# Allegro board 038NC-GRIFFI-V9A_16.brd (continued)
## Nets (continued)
S16_VBAT_F: SITE16.F1(VBAT_F) UNK16CS1.1 UNK16K10.3 UNK16K11.3 UNK16K12.3 UNK16TP_VBAT_F.1
S16_VBAT_K11C: UNK16C6.1 UNK16K11.4
S16_VBAT_K12: UNK16C9.1 UNK16K12.4 UNK16TP_REF_5V.1 UNK16U1.6
S16_VBAT_S: SITE16.S1(VBAT_S) UNK16K10.6 UNK16K12.6 UNK16TP_VBAT_S.1
S16_VBUS_CK: UNK16C2.2 UNK16K1.3
S16_VSET: SITE16.F8(VSET_F) SITE16.S8(VSET_S) UNK16K3.3 UNK16TP_VEST.1
S16_VSET_K3R: UNK16K3.2 UNK16R1.2
SCOPE_TP0: SLOT0.B16
SCOPE_TP1: SLOT0.A16
SDUABUS1: SLOT0.F41
SDUABUS2: SLOT0.E41
SDUABUS3: SLOT0.F39
SDUABUS4: SLOT0.E39
SDUCAL1_HF: SLOT0.A41
SDUCAL1_HG: SLOT0.A40 SLOT0.B40 SLOT0.C41
SDUCAL1_HS: SLOT0.B41
SDUCAL1_LF: SLOT0.A39
SDUCAL1_LS: SLOT0.B39
SDUCBIT1: SLOT0.D39 UNK1K7.8 UNK2K7.8
SDUCBIT2: SLOT0.C39 UNK1K6.8 UNK2K6.8
SDUCBIT3: SLOT0.F37 UNK1K4.8 UNK2K4.8
SDUCBIT4: SLOT0.E37 UNK1K5.8 UNK2K5.8
SDUCBIT5: SLOT0.D37 UNK1K3.8 UNK2K3.8
SDUCBIT6: SLOT0.C37 UNK1K10.8 UNK2K10.8
SDUCBIT7: SLOT0.F35 UNK1K12.8 UNK2K12.8
SDUCBIT8: SLOT0.E35 UNK1K11.8 UNK2K11.8
SDUCBIT9: SLOT0.D35 UNK1K13.8 UNK2K13.8
SDUCBIT10: SLOT0.C35 UNK1K8.8 UNK2K8.8
SDUCBIT11: SLOT0.B35 UNK1K1.8 UNK2K1.8
SDUCBIT12: SLOT0.A35 UNK1K14.8 UNK2K14.8
SDUCBIT13: SLOT0.F33 UNK1K9.8 UNK2K9.8
SDUCBIT14: SLOT0.E33 UNK1K2.8 UNK2K2.8
SDUCBIT15: SLOT0.D33
SDUCBIT16: SLOT0.C33
SDUCBIT17: SLOT0.B33 UNK3K7.8 UNK4K7.8
SDUCBIT18: SLOT0.A33 UNK3K6.8 UNK4K6.8
SDUCBIT19: SLOT0.F31 UNK3K4.8 UNK4K4.8
SDUCBIT20: SLOT0.E31 UNK3K5.8 UNK4K5.8
SDUCBIT21: SLOT0.D31 UNK3K3.8 UNK4K3.8
SDUCBIT22: SLOT0.C31 UNK3K10.8 UNK4K10.8
SDUCBIT23: SLOT0.B31 UNK3K12.8 UNK4K12.8
SDUCBIT24: SLOT0.A31 UNK3K11.8 UNK4K11.8
SDUCBIT25: SLOT0.F29 UNK3K13.8 UNK4K13.8
SDUCBIT26: SLOT0.E29 UNK3K8.8 UNK4K8.8
SDUCBIT27: SLOT0.D29 UNK3K1.8 UNK4K1.8
SDUCBIT28: SLOT0.C29 UNK3K14.8 UNK4K14.8
SDUCBIT29: SLOT0.B29 UNK3K9.8 UNK4K9.8
SDUCBIT30: SLOT0.A29 UNK3K2.8 UNK4K2.8
SDUCBIT31: SLOT0.F27
SDUCBIT32: SLOT0.E27
SDUCBIT33: SLOT0.D27 UNK5K7.8 UNK6K7.8
SDUCBIT34: SLOT0.C27 UNK5K6.8 UNK6K6.8
SDUCBIT35: SLOT0.B27 UNK5K4.8 UNK6K4.8
SDUCBIT36: SLOT0.A27 UNK5K5.8 UNK6K5.8
SDUCBIT37: SLOT0.F25 UNK5K3.8 UNK6K3.8
SDUCBIT38: SLOT0.E25 UNK5K10.8 UNK6K10.8
SDUCBIT39: SLOT0.D25 UNK5K12.8 UNK6K12.8
SDUCBIT40: SLOT0.C25 UNK5K11.8 UNK6K11.8
SDUCBIT41: SLOT0.B25 UNK5K13.8 UNK6K13.8
SDUCBIT42: SLOT0.A25 UNK5K8.8 UNK6K8.8
SDUCBIT43: SLOT0.F23 UNK5K1.8 UNK6K1.8
SDUCBIT44: SLOT0.E23 UNK5K14.8 UNK6K14.8
SDUCBIT45: SLOT0.D23 UNK5K9.8 UNK6K9.8
SDUCBIT46: SLOT0.C23 UNK5K2.8 UNK6K2.8
SDUCBIT47: SLOT0.B23
SDUCBIT48: SLOT0.A23
SDUCBIT49: SLOT0.F21 UNK7K7.8 UNK8K7.8
SDUCBIT50: SLOT0.E21 UNK7K6.8 UNK8K6.8
SDUCBIT51: SLOT0.D21 UNK7K4.8 UNK8K4.8
SDUCBIT52: SLOT0.C21 UNK7K5.8 UNK8K5.8
SDUCBIT53: SLOT0.B21 UNK7K3.8 UNK8K3.8
SDUCBIT54: SLOT0.A21 UNK7K10.8 UNK8K10.8
SDUCBIT55: SLOT0.F19 UNK7K12.8 UNK8K12.8
SDUCBIT56: SLOT0.E19 UNK7K11.8 UNK8K11.8
SDUCBIT57: SLOT0.D19 UNK7K13.8 UNK8K13.8
SDUCBIT58: SLOT0.C19 UNK7K8.8 UNK8K8.8
SDUCBIT59: SLOT0.B19 UNK7K1.8 UNK8K1.8
SDUCBIT60: SLOT0.A19 UNK7K14.8 UNK8K14.8
SDUCBIT61: SLOT0.F17 UNK7K9.8 UNK8K9.8
SDUCBIT62: SLOT0.E17 UNK7K2.8 UNK8K2.8
SDUCBIT63: SLOT0.D17
SDUCBIT64: SLOT0.F7
SDUCBIT65: SLOT0.E7 UNK9K7.8 UNK10K7.8
SDUCBIT66: SLOT0.D7 UNK9K6.8 UNK10K6.8
SDUCBIT67: SLOT0.C7 UNK9K4.8 UNK10K4.8
SDUCBIT68: SLOT0.B7 UNK9K5.8 UNK10K5.8
SDUCBIT69: SLOT0.A7 UNK9K3.8 UNK10K3.8
SDUCBIT70: SLOT0.F5 UNK9K10.8 UNK10K10.8
SDUCBIT71: SLOT0.E5 UNK9K12.8 UNK10K12.8
SDUCBIT72: SLOT0.D5 UNK9K11.8 UNK10K11.8
SDUCBIT73: SLOT0.C5 UNK9K13.8 UNK10K13.8
SDUCBIT74: SLOT0.B5 UNK9K8.8 UNK10K8.8
SDUCBIT75: SLOT0.A5 UNK9K1.8 UNK10K1.8
SDUCBIT76: SLOT0.F3 UNK9K14.8 UNK10K14.8
SDUCBIT77: SLOT0.E3 UNK9K9.8 UNK10K9.8
SDUCBIT78: SLOT0.D3 UNK9K2.8 UNK10K2.8
SDUCBIT79: SLOT0.C3
SDUCBIT80: SLOT0.B3
SDUCBIT81: SLOT0.A3 UNK11K7.8 UNK12K7.8
SDUCBIT82: SLOT0.G24 UNK11K6.8 UNK12K6.8
SDUCBIT83: SLOT0.F24 UNK11K4.8 UNK12K4.8
SDUCBIT84: SLOT0.E24 UNK11K5.8 UNK12K5.8
SDUCBIT85: SLOT0.D24 UNK11K3.8 UNK12K3.8
SDUCBIT86: SLOT0.C24 UNK11K10.8 UNK12K10.8
SDUCBIT87: SLOT0.B24 UNK11K12.8 UNK12K12.8
SDUCBIT88: SLOT0.F26 UNK11K11.8 UNK12K11.8
SDUCBIT89: SLOT0.E26 UNK11K13.8 UNK12K13.8
SDUCBIT90: SLOT0.D26 UNK11K8.8 UNK12K8.8
SDUCBIT91: SLOT0.C26 UNK11K1.8 UNK12K1.8
SDUCBIT92: SLOT0.B26 UNK11K14.8 UNK12K14.8
SDUCBIT93: SLOT0.A26 UNK11K9.8 UNK12K9.8
SDUCBIT94: SLOT0.G28 UNK11K2.8 UNK12K2.8
SDUCBIT95: SLOT0.F28
SDUCBIT96: SLOT0.E28
SDUCBIT97: SLOT0.D28 UNK13K7.8 UNK14K7.8
SDUCBIT98: SLOT0.C28 UNK13K6.8 UNK14K6.8
SDUCBIT99: SLOT0.B28 UNK13K4.8 UNK14K4.8
SDUCBIT100: SLOT0.F30 UNK13K5.8 UNK14K5.8
SDUCBIT101: SLOT0.E30 UNK13K3.8 UNK14K3.8
SDUCBIT102: SLOT0.D30 UNK13K10.8 UNK14K10.8
SDUCBIT103: SLOT0.C30 UNK13K12.8 UNK14K12.8
SDUCBIT104: SLOT0.B30 UNK13K11.8 UNK14K11.8
SDUCBIT105: SLOT0.A30 UNK13K13.8 UNK14K13.8
SDUCBIT106: SLOT0.G32 UNK13K8.8 UNK14K8.8
SDUCBIT107: SLOT0.F32 UNK13K1.8 UNK14K1.8
SDUCBIT108: SLOT0.E32 UNK13K14.8 UNK14K14.8
SDUCBIT109: SLOT0.D32 UNK13K9.8 UNK14K9.8
SDUCBIT110: SLOT0.C32 UNK13K2.8 UNK14K2.8
SDUCBIT111: SLOT0.B32
SDUCBIT112: SLOT0.F34
SDUCBIT113: SLOT0.E34 UNK15K7.8 UNK16K7.8
SDUCBIT114: SLOT0.D34 UNK15K6.8 UNK16K6.8
SDUCBIT115: SLOT0.C34 UNK15K4.8 UNK16K4.8
SDUCBIT116: SLOT0.B34 UNK15K5.8 UNK16K5.8
SDUCBIT117: SLOT0.A34 UNK15K3.8 UNK16K3.8
SDUCBIT118: SLOT0.G36 UNK15K10.8 UNK16K10.8
SDUCBIT119: SLOT0.F36 UNK15K12.8 UNK16K12.8
SDUCBIT120: SLOT0.E36 UNK15K11.8 UNK16K11.8
SDUCBIT121: SLOT0.D36 UNK15K13.8 UNK16K13.8
SDUCBIT122: SLOT0.C36 UNK15K8.8 UNK16K8.8
SDUCBIT123: SLOT0.B36 UNK15K1.8 UNK16K1.8
SDUCBIT124: SLOT0.G38 UNK15K14.8 UNK16K14.8
SDUCBIT125: SLOT0.F38 UNK15K9.8 UNK16K9.8
SDUCBIT126: SLOT0.E38 UNK15K2.8 UNK16K2.8
SDUCBIT127: SLOT0.D38
SDUCBIT128: SLOT0.C38
SDUI2C1_SYS_P3V3: R22.2 SLOT0.G16
SDUI2C1_SYS_SCLK: R24.2 SLOT0.G14 TP_EPP_SCLK.1(TP)
SDUI2C1_SYS_SDA: R23.2 SLOT0.G18
SDUI2C1_USER_SCLK: R8.2 SLOT0.F14 TP_USER_SCLK1.1(TP) U4.1(SCL)
SDUI2C1_USER_SDA: R7.2 SLOT0.F16 TP_USER_SDA1.1(TP) U4.2(SDA)
SDUP5V1: BC1.1 BC2.1 FUSE2.1 SLOT0.A2 SLOT0.A4 SLOT0.B2 SLOT0.B4 SLOT0.C2 T_USER_5V.1(TP) USER_5V1.1(A)
SDUSPI1_CS_N: SLOT0.E16
SDUSPI1_MISO: SLOT0.F18
SDUSPI1_MOSI: SLOT0.E18
SDUSPI1_SCLK: SLOT0.E14
SDUSYNC1: SLOT0.C14
SDUSYNC2: SLOT0.B14
SPARE0: SLOT0.A8
SPARE1: SLOT0.G22
SPARE2: SLOT0.A20
SPARE3: SLOT0.G26
SPARE4: SLOT0.A24
SPARE5: SLOT0.G30
SPARE6: SLOT0.A28
SPARE7: SLOT0.G34
SPARE8: SLOT0.A32
SPARE9: SLOT0.G40
SPARE10: SLOT0.A36
SPARE11: SLOT0.F40
SPARE12: SLOT0.C40
SPARE13: SLOT0.E40
SPARE14: SLOT0.D40
TMU_INPUT_A: SLOT0.B12
TMU_INPUT_B: SLOT0.D12
TMU_REF_GND: SLOT0.A37 UNK0BS1.1
TMU_TRIGGER: SLOT0.F12
U4_CT: R9.2 U4.10(CT)
U4_INT: R10.2 U4.9(INT)
U6_SCL: R24.1 U6.6(SCL)
U6_SDA: R21.2 R23.1 TP_EPP_SDA.1(TP) U6.5(SDA)
U6_VCC: C14.2 R21.1 R22.1 TP_EPP_VCC.1(TP) U6.8(VCC)
U46_ADJ: R376.2 R381.1 U46.1(ADJ)
U46_R: R381.2 R382.1
U47_ADJ: R378.1 R383.2 U47.1(ADJ)
UGND: BC1.2 BC2.2 BC3.1 BC4.1 BC5.2 BC6.2 BC7.2 BC8.2 BC10.2 BC11.2 BC12.1 BC13.1 BD1.2 BD2.2 C102.2
USER_12V: BC7.1 BC8.1 SLOT0.F6 SLOT0.G6 T_USER_12V.1(TP) UNK1C7.1 UNK1C8.1 UNK1K1.1 UNK1K2.1 UNK1K3.1 UNK1K4.1 UNK1K5.1 UNK1K6.1 UNK1K7.1 UNK1K8.1 UNK1K9.1 UNK1K10.1 UNK1K11.1 UNK1K12.1 UNK1K13.1 UNK1K14.1 UNK1U1.2 UNK2C7.1 UNK2C8.1 UNK2K1.1 UNK2K2.1 UNK2K3.1 UNK2K4.1 UNK2K5.1 UNK2K6.1 UNK2K7.1 UNK2K8.1 UNK2K9.1 UNK2K10.1 UNK2K11.1 UNK2K12.1 UNK2K13.1 UNK2K14.1 UNK2U1.2 UNK3C7.1 UNK3C8.1 UNK3K1.1 UNK3K2.1 UNK3K3.1 UNK3K4.1 UNK3K5.1 UNK3K6.1 UNK3K7.1 UNK3K8.1 UNK3K9.1 UNK3K10.1 UNK3K11.1 UNK3K12.1 UNK3K13.1 UNK3K14.1 UNK3U1.2 UNK4C7.1 UNK4C8.1 UNK4K1.1 UNK4K2.1 UNK4K3.1 UNK4K4.1 UNK4K5.1 UNK4K6.1 UNK4K7.1 UNK4K8.1 UNK4K9.1 UNK4K10.1 UNK4K11.1 UNK4K12.1 UNK4K13.1 UNK4K14.1 UNK4U1.2 UNK5C7.1 UNK5C8.1 UNK5K1.1 UNK5K2.1 UNK5K3.1 UNK5K4.1 UNK5K5.1 UNK5K6.1 UNK5K7.1 UNK5K8.1 UNK5K9.1 UNK5K10.1 UNK5K11.1 UNK5K12.1 UNK5K13.1 UNK5K14.1 UNK5U1.2 UNK6C7.1 UNK6C8.1 UNK6K1.1 UNK6K2.1 UNK6K3.1 UNK6K4.1 UNK6K5.1 UNK6K6.1 UNK6K7.1 UNK6K8.1 UNK6K9.1 UNK6K10.1 UNK6K11.1 UNK6K12.1 UNK6K13.1 UNK6K14.1 UNK6U1.2 UNK7C7.1 UNK7C8.1 UNK7K1.1 UNK7K2.1 UNK7K3.1 UNK7K4.1 UNK7K5.1 UNK7K6.1 UNK7K7.1 UNK7K8.1 UNK7K9.1 UNK7K10.1 UNK7K11.1 UNK7K12.1 UNK7K13.1 UNK7K14.1 UNK7U1.2 UNK8C7.1 UNK8C8.1 UNK8K1.1 UNK8K2.1 UNK8K3.1 UNK8K4.1 UNK8K5.1 UNK8K6.1 UNK8K7.1 UNK8K8.1 UNK8K9.1 UNK8K10.1 UNK8K11.1 UNK8K12.1 UNK8K13.1 UNK8K14.1 UNK8U1.2 UNK9C7.1 UNK9C8.1 UNK9K1.1 UNK9K2.1 UNK9K3.1 UNK9K4.1 UNK9K5.1 UNK9K6.1 UNK9K7.1 UNK9K8.1 UNK9K9.1 UNK9K10.1 UNK9K11.1 UNK9K12.1 UNK9K13.1 UNK9K14.1 UNK9U1.2 UNK10C7.1 UNK10C8.1 UNK10K1.1 UNK10K2.1 UNK10K3.1 UNK10K4.1 UNK10K5.1 UNK10K6.1 UNK10K7.1 UNK10K8.1 UNK10K9.1 UNK10K10.1 UNK10K11.1 UNK10K12.1 UNK10K13.1 UNK10K14.1 UNK10U1.2 UNK11C7.1 UNK11C8.1 UNK11K1.1 UNK11K2.1 UNK11K3.1 UNK11K4.1 UNK11K5.1 UNK11K6.1 UNK11K7.1 UNK11K8.1 UNK11K9.1 UNK11K10.1 UNK11K11.1 UNK11K12.1 UNK11K13.1 UNK11K14.1 UNK11U1.2 UNK12C7.1 UNK12C8.1 UNK12K1.1 UNK12K2.1 UNK12K3.1 UNK12K4.1 UNK12K5.1 UNK12K6.1 UNK12K7.1 UNK12K8.1 UNK12K9.1 UNK12K10.1 UNK12K11.1 UNK12K12.1 UNK12K13.1 UNK12K14.1 UNK12U1.2 UNK13C7.1 UNK13C8.1 UNK13K1.1 UNK13K2.1 UNK13K3.1 UNK13K4.1 UNK13K5.1 UNK13K6.1 UNK13K7.1 UNK13K8.1 UNK13K9.1 UNK13K10.1 UNK13K11.1 UNK13K12.1 UNK13K13.1 UNK13K14.1 UNK13U1.2 UNK14C7.1 UNK14C8.1 UNK14K1.1 UNK14K2.1 UNK14K3.1 UNK14K4.1 UNK14K5.1 UNK14K6.1 UNK14K7.1 UNK14K8.1 UNK14K9.1 UNK14K10.1 UNK14K11.1 UNK14K12.1 UNK14K13.1 UNK14K14.1 UNK14U1.2 UNK15C7.1 UNK15C8.1 UNK15K1.1 UNK15K2.1 UNK15K3.1 UNK15K4.1 UNK15K5.1 UNK15K6.1 UNK15K7.1 UNK15K8.1 UNK15K9.1 UNK15K10.1 UNK15K11.1 UNK15K12.1 UNK15K13.1 UNK15K14.1 UNK15U1.2 UNK16C7.1 UNK16C8.1 UNK16K1.1 UNK16K2.1 UNK16K3.1 UNK16K4.1 UNK16K5.1 UNK16K6.1 UNK16K7.1 UNK16K8.1 UNK16K9.1 UNK16K10.1 UNK16K11.1 UNK16K12.1 UNK16K13.1 UNK16K14.1 UNK16U1.2 USER_12V1.1(A)
USER_-5V: BC3.2 BC4.2 BR2.2 SLOT0.C4 SLOT0.D4 SLOT0.E4 SLOT0.F4 SLOT0.G4 T_USER_-5V.1(TP)
VI_433_6-CH1BP: SLOT6.B35
VI_433_6-CH1F: SLOT6.F35
VI_433_6-CH1GS: SLOT6.A35
VI_433_6-CH1S: SLOT6.C35
VI_434_6-CH2BP: SLOT6.B33
VI_434_6-CH2F: SLOT6.F33
VI_434_6-CH2GS: SLOT6.A33
VI_434_6-CH2S: SLOT6.C33
VI_435_6-CH3BP: SLOT6.B31
VI_435_6-CH3F: SLOT6.F31
VI_435_6-CH3GS: SLOT6.A31
VI_435_6-CH3S: SLOT6.C31
VI_436_6-CH4BP: SLOT6.B29
VI_436_6-CH4F: SLOT6.F29
VI_436_6-CH4GS: SLOT6.A29
VI_436_6-CH4S: SLOT6.C29
VI_437_6-CH5BP: SLOT6.B27
VI_437_6-CH5F: SLOT6.F27
VI_437_6-CH5GS: SLOT6.A27
VI_437_6-CH5S: SLOT6.C27
VI_438_6-CH6BP: SLOT6.B25
VI_438_6-CH6F: SLOT6.F25
VI_438_6-CH6GS: SLOT6.A25
VI_438_6-CH6S: SLOT6.C25
VI_439_6-CH7BP: SLOT6.B23
VI_439_6-CH7F: SLOT6.F23
VI_439_6-CH7GS: SLOT6.A23
VI_439_6-CH7S: SLOT6.C23
VI_440_6-CH8BP: SLOT6.B21
VI_440_6-CH8F: SLOT6.F21
VI_440_6-CH8GS: SLOT6.A21
VI_440_6-CH8S: SLOT6.C21
VI_441_6-CH9BP: SLOT6.D37
VI_441_6-CH9F: SLOT6.F37
VI_441_6-CH9GS: SLOT6.C37
VI_441_6-CH9S: SLOT6.E37
VI_442_6-CH10BP: SLOT6.D33
VI_442_6-CH10F: SLOT6.E35
VI_442_6-CH10GS: SLOT6.B37
VI_442_6-CH10S: SLOT6.E33
VI_443_6-CH11BP: SLOT6.D29
VI_443_6-CH11F: SLOT6.E31
VI_443_6-CH11GS: SLOT6.A37
VI_443_6-CH11S: SLOT6.E29
VI_444_6-CH12BP: SLOT6.D25
VI_444_6-CH12F: SLOT6.E27
VI_444_6-CH12GS: SLOT6.B19
VI_444_6-CH12S: SLOT6.E25
VI_445_6-CH13BP: SLOT6.D21
VI_445_6-CH13F: SLOT6.E23
VI_445_6-CH13GS: SLOT6.A19
VI_445_6-CH13S: SLOT6.E21
VI_446_6-CH14BP: SLOT6.D19
VI_446_6-CH14F: SLOT6.F19
VI_446_6-CH14GS: SLOT6.C19
VI_446_6-CH14S: SLOT6.E19
VI_447_6-CH15BP: SLOT6.D17
VI_447_6-CH15F: SLOT6.F17
VI_447_6-CH15GS: SLOT6.A17
VI_447_6-CH15S: SLOT6.E17
VI_448_6-CH16BP: SLOT6.C17
VI_448_6-CH16F: SLOT6.E15
VI_448_6-CH16GS: SLOT6.B17
VI_448_6-CH16S: SLOT6.D15
VI_449_6-CH17BP: SLOT6.B15
VI_449_6-CH17F: SLOT6.F15
VI_449_6-CH17GS: SLOT6.A15
VI_449_6-CH17S: SLOT6.C15
VI_450_6-CH18BP: SLOT6.D13
VI_450_6-CH18F: SLOT6.F13
VI_450_6-CH18GS: SLOT6.A13
VI_450_6-CH18S: SLOT6.E13
VI_451_6-CH19BP: SLOT6.D11
VI_451_6-CH19F: SLOT6.F11
VI_451_6-CH19GS: SLOT6.B13
VI_451_6-CH19S: SLOT6.E11
VI_452_6-CH20BP: SLOT6.C11
VI_452_6-CH20F: SLOT6.E9
VI_452_6-CH20GS: SLOT6.C13
VI_452_6-CH20S: SLOT6.D9
VI_453_6-CH21BP: SLOT6.B9
VI_453_6-CH21F: SLOT6.F9
VI_453_6-CH21GS: SLOT6.B11
VI_453_6-CH21S: SLOT6.C9
VI_454_6-CH22BP: SLOT6.D7
VI_454_6-CH22F: SLOT6.F7
VI_454_6-CH22GS: SLOT6.A11
VI_454_6-CH22S: SLOT6.E7
VI_455_6-CH23BP: SLOT6.D5
VI_455_6-CH23F: SLOT6.F5
VI_455_6-CH23GS: SLOT6.A9
VI_455_6-CH23S: SLOT6.E5
VI_456_6-CH24BP: SLOT6.D3
VI_456_6-CH24F: SLOT6.F3
VI_456_6-CH24GS: SLOT6.A7
VI_456_6-CH24S: SLOT6.E3
VI_457_6-CH25BP: SLOT6.D1
VI_457_6-CH25F: SLOT6.F1
VI_457_6-CH25GS: SLOT6.B7
VI_457_6-CH25S: SLOT6.E1
VI_458_6-CH26BP: SLOT6.C3
VI_458_6-CH26F: SLOT6.G4
VI_458_6-CH26GS: SLOT6.C7
VI_458_6-CH26S: SLOT6.C1
VI_459_6-CH27BP: SLOT6.D2
VI_459_6-CH27F: SLOT6.F2
VI_459_6-CH27GS: SLOT6.C5
VI_459_6-CH27S: SLOT6.C4
VI_460_6-CH28BP: SLOT6.B3
VI_460_6-CH28F: SLOT6.A4
VI_460_6-CH28GS: SLOT6.B5
VI_460_6-CH28S: SLOT6.B1
VI_461_6-CH29BP: SLOT6.A3
VI_461_6-CH29F: SLOT6.B2
VI_461_6-CH29GS: SLOT6.A5
VI_461_6-CH29S: SLOT6.A1
VI_462_6-CH30BP: SLOT6.A60
VI_462_6-CH30F: SLOT6.B62
VI_462_6-CH30GS: SLOT6.B58
VI_462_6-CH30S: SLOT6.A61
VI_463_6-CH31BP: SLOT6.A59
VI_463_6-CH31F: SLOT6.C62
VI_463_6-CH31GS: SLOT6.A57
VI_463_6-CH31S: SLOT6.B61
VI_464_6-CH32BP: SLOT6.E60
VI_464_6-CH32F: SLOT6.F62
VI_464_6-CH32GS: SLOT6.C60
VI_464_6-CH32S: SLOT6.F61
VI_465_6-CH33BP: SLOT6.D61
VI_465_6-CH33F: SLOT6.E62
VI_465_6-CH33GS: SLOT6.C61
VI_465_6-CH33S: SLOT6.E61
VI_466_6-CH34BP: SLOT6.C59
VI_466_6-CH34F: SLOT6.F59
VI_466_6-CH34GS: SLOT6.B59
VI_466_6-CH34S: SLOT6.D59
VI_467_6-CH35BP: SLOT6.F58
VI_467_6-CH35F: SLOT6.G60
VI_467_6-CH35GS: SLOT6.D58
VI_467_6-CH35S: SLOT6.E59
VI_468_6-CH36BP: SLOT6.C57
VI_468_6-CH36F: SLOT6.E57
VI_468_6-CH36GS: SLOT6.B57
VI_468_6-CH36S: SLOT6.D57
VI_469_6-CH37BP: SLOT6.E56
VI_469_6-CH37F: SLOT6.F57
VI_469_6-CH37GS: SLOT6.C56
VI_469_6-CH37S: SLOT6.G56
VI_470_6-CH38BP: SLOT6.D55
VI_470_6-CH38F: SLOT6.F55
VI_470_6-CH38GS: SLOT6.B55
VI_470_6-CH38S: SLOT6.E55
VI_471_6-CH39BP: SLOT6.B54
VI_471_6-CH39F: SLOT6.E52
VI_471_6-CH39GS: SLOT6.A55
VI_471_6-CH39S: SLOT6.C55
VI_472_6-CH40BP: SLOT6.D54
VI_472_6-CH40F: SLOT6.G52
VI_472_6-CH40GS: SLOT6.A56
VI_472_6-CH40S: SLOT6.F54
VI_473_6-CH41BP: SLOT6.B53
VI_473_6-CH41F: SLOT6.F53
VI_473_6-CH41GS: SLOT6.A53
VI_473_6-CH41S: SLOT6.C53
VI_474_6-CH42BP: SLOT6.D53
VI_474_6-CH42F: SLOT6.F51
VI_474_6-CH42GS: SLOT6.A52
VI_474_6-CH42S: SLOT6.E53
VI_475_6-CH43BP: SLOT6.C51
VI_475_6-CH43F: SLOT6.E51
VI_475_6-CH43GS: SLOT6.C52
VI_475_6-CH43S: SLOT6.D51
VI_476_6-CH44BP: SLOT6.D50
VI_476_6-CH44F: SLOT6.F49
VI_476_6-CH44GS: SLOT6.A51
VI_476_6-CH44S: SLOT6.F50
VI_477_6-CH45BP: SLOT6.B50
VI_477_6-CH45F: SLOT6.E49
VI_477_6-CH45GS: SLOT6.B51
VI_477_6-CH45S: SLOT6.D49
VI_478_6-CH46BP: SLOT6.B49
VI_478_6-CH46F: SLOT6.G48
VI_478_6-CH46GS: SLOT6.A49
VI_478_6-CH46S: SLOT6.C49
VI_479_6-CH47BP: SLOT6.D47
VI_479_6-CH47F: SLOT6.F47
VI_479_6-CH47GS: SLOT6.A48
VI_479_6-CH47S: SLOT6.E47
VI_480_6-CH48BP: SLOT6.C45
VI_480_6-CH48F: SLOT6.F45
VI_480_6-CH48GS: SLOT6.C48
VI_480_6-CH48S: SLOT6.D46
VI_481_6-CH49BP: SLOT6.C47
VI_481_6-CH49F: SLOT6.F46
VI_481_6-CH49GS: SLOT6.E48
VI_481_6-CH49S: SLOT6.E45
VI_482_6-CH50BP: SLOT6.B46
VI_482_6-CH50F: SLOT6.G44
VI_482_6-CH50GS: SLOT6.B47
VI_482_6-CH50S: SLOT6.B45
VI_483_6-CH51BP: SLOT6.D45
VI_483_6-CH51F: SLOT6.F41
VI_483_6-CH51GS: SLOT6.A47
VI_483_6-CH51S: SLOT6.E43
VI_484_6-CH52BP: SLOT6.D43
VI_484_6-CH52F: SLOT6.F43
VI_484_6-CH52GS: SLOT6.A45
VI_484_6-CH52S: SLOT6.F42
VI_485_6-CH53BP: SLOT6.D42
VI_485_6-CH53F: SLOT6.G40
VI_485_6-CH53GS: SLOT6.A44
VI_485_6-CH53S: SLOT6.E41
VI_486_6-CH54BP: SLOT6.C41
VI_486_6-CH54F: SLOT6.F39
VI_486_6-CH54GS: SLOT6.C44
VI_486_6-CH54S: SLOT6.D41
VI_487_6-CH55BP: SLOT6.B41
VI_487_6-CH55F: SLOT6.F38
VI_487_6-CH55GS: SLOT6.E44
VI_487_6-CH55S: SLOT6.B39
VI_488_6-CH56BP: SLOT6.C39
VI_488_6-CH56F: SLOT6.E39
VI_488_6-CH56GS: SLOT6.C43
VI_488_6-CH56S: SLOT6.D39
VI_489_6-CH57BP: SLOT6.A41
VI_489_6-CH57F: SLOT6.E40
VI_489_6-CH57GS: SLOT6.B43
VI_489_6-CH57S: SLOT6.A39
VI_490_6-CH58BP: SLOT6.B42
VI_490_6-CH58F: SLOT6.C40
VI_490_6-CH58GS: SLOT6.A43
VI_490_6-CH58S: SLOT6.A40
VI_491_6-CH59BP: SLOT6.C36
VI_491_6-CH59F: SLOT6.G36
VI_491_6-CH59GS: SLOT6.D38
VI_491_6-CH59S: SLOT6.E36
VI_492_6-CH60BP: SLOT6.D34
VI_492_6-CH60F: SLOT6.G32
VI_492_6-CH60GS: SLOT6.B38
VI_492_6-CH60S: SLOT6.E32
VI_493_6-CH61BP: SLOT6.E24
VI_493_6-CH61F: SLOT6.E28
VI_493_6-CH61GS: SLOT6.A36
VI_493_6-CH61S: SLOT6.F26
VI_494_6-CH62BP: SLOT6.F18
VI_494_6-CH62F: SLOT6.G20
VI_494_6-CH62GS: SLOT6.B10
VI_494_6-CH62S: SLOT6.E16
VI_495_6-CH63BP: SLOT6.E12
VI_495_6-CH63F: SLOT6.F14
VI_495_6-CH63GS: SLOT6.A8
VI_495_6-CH63S: SLOT6.D10
VI_496_6-CH64BP: SLOT6.E8
VI_496_6-CH64F: SLOT6.G8
VI_496_6-CH64GS: SLOT6.C8
VI_496_6-CH64S: SLOT6.F6
VI_497_6-CH65BP: SLOT6.B34
VI_497_6-CH65F: SLOT6.F34
VI_497_6-CH65GS: SLOT6.A32
VI_497_6-CH65S: SLOT6.C32
VI_498_6-CH66BP: SLOT6.D30
VI_498_6-CH66F: SLOT6.F30
VI_498_6-CH66GS: SLOT6.B30
VI_498_6-CH66S: SLOT6.C28
VI_499_6-CH67BP: SLOT6.B26
VI_499_6-CH67F: SLOT6.G28
VI_499_6-CH67GS: SLOT6.A28
VI_499_6-CH67S: SLOT6.D26
VI_500_6-CH68BP: SLOT6.C24
VI_500_6-CH68F: SLOT6.G24
VI_500_6-CH68GS: SLOT6.A24
VI_500_6-CH68S: SLOT6.B22
VI_501_6-CH69BP: SLOT6.C20
VI_501_6-CH69F: SLOT6.F22
VI_501_6-CH69GS: SLOT6.A20
VI_501_6-CH69S: SLOT6.D22
VI_502_6-CH70BP: SLOT6.D18
VI_502_6-CH70F: SLOT6.G16
VI_502_6-CH70GS: SLOT6.B18
VI_502_6-CH70S: SLOT6.E20
VI_503_6-CH71BP: SLOT6.C16
VI_503_6-CH71F: SLOT6.G12
VI_503_6-CH71GS: SLOT6.A16
VI_503_6-CH71S: SLOT6.B14
VI_504_6-CH72BP: SLOT6.C12
VI_504_6-CH72F: SLOT6.F10
VI_504_6-CH72GS: SLOT6.A12
VI_504_6-CH72S: SLOT6.D14
VI_505_7-CH1BP: SLOT7.B35
VI_505_7-CH1F: SLOT7.F35
VI_505_7-CH1GS: SLOT7.A35
VI_505_7-CH1S: SLOT7.C35
VI_506_7-CH2BP: SLOT7.B33
VI_506_7-CH2F: SLOT7.F33
VI_506_7-CH2GS: SLOT7.A33
VI_506_7-CH2S: SLOT7.C33
VI_507_7-CH3BP: SLOT7.B31
VI_507_7-CH3F: SLOT7.F31
VI_507_7-CH3GS: SLOT7.A31
VI_507_7-CH3S: SLOT7.C31
VI_508_7-CH4BP: SLOT7.B29
VI_508_7-CH4F: SLOT7.F29
VI_508_7-CH4GS: SLOT7.A29
VI_508_7-CH4S: SLOT7.C29
VI_509_7-CH5BP: SLOT7.B27
VI_509_7-CH5F: SLOT7.F27
VI_509_7-CH5GS: SLOT7.A27
VI_509_7-CH5S: SLOT7.C27
VI_510_7-CH6BP: SLOT7.B25
VI_510_7-CH6F: SLOT7.F25
VI_510_7-CH6GS: SLOT7.A25
VI_510_7-CH6S: SLOT7.C25
VI_511_7-CH7BP: SLOT7.B23
VI_511_7-CH7F: SLOT7.F23
VI_511_7-CH7GS: SLOT7.A23
VI_511_7-CH7S: SLOT7.C23
VI_512_7-CH8BP: SLOT7.B21
VI_512_7-CH8F: SLOT7.F21
VI_512_7-CH8GS: SLOT7.A21
VI_512_7-CH8S: SLOT7.C21
VI_513_7-CH9BP: SLOT7.D37
VI_513_7-CH9F: SLOT7.F37
VI_513_7-CH9GS: SLOT7.C37
VI_513_7-CH9S: SLOT7.E37
VI_514_7-CH10BP: SLOT7.D33
VI_514_7-CH10F: SLOT7.E35
VI_514_7-CH10GS: SLOT7.B37
VI_514_7-CH10S: SLOT7.E33
VI_515_7-CH11BP: SLOT7.D29
VI_515_7-CH11F: SLOT7.E31
VI_515_7-CH11GS: SLOT7.A37
VI_515_7-CH11S: SLOT7.E29
VI_516_7-CH12BP: SLOT7.D25
VI_516_7-CH12F: SLOT7.E27
VI_516_7-CH12GS: SLOT7.B19
VI_516_7-CH12S: SLOT7.E25
VI_517_7-CH13BP: SLOT7.D21
VI_517_7-CH13F: SLOT7.E23
VI_517_7-CH13GS: SLOT7.A19
VI_517_7-CH13S: SLOT7.E21
VI_518_7-CH14BP: SLOT7.D19
VI_518_7-CH14F: SLOT7.F19
VI_518_7-CH14GS: SLOT7.C19
VI_518_7-CH14S: SLOT7.E19
VI_519_7-CH15BP: SLOT7.D17
VI_519_7-CH15F: SLOT7.F17
VI_519_7-CH15GS: SLOT7.A17
VI_519_7-CH15S: SLOT7.E17
VI_520_7-CH16BP: SLOT7.C17
VI_520_7-CH16F: SLOT7.E15
VI_520_7-CH16GS: SLOT7.B17
VI_520_7-CH16S: SLOT7.D15
VI_521_7-CH17BP: SLOT7.B15
VI_521_7-CH17F: SLOT7.F15
VI_521_7-CH17GS: SLOT7.A15
VI_521_7-CH17S: SLOT7.C15
VI_522_7-CH18BP: SLOT7.D13
VI_522_7-CH18F: SLOT7.F13
VI_522_7-CH18GS: SLOT7.A13
VI_522_7-CH18S: SLOT7.E13
VI_523_7-CH19BP: SLOT7.D11
VI_523_7-CH19F: SLOT7.F11
VI_523_7-CH19GS: SLOT7.B13
VI_523_7-CH19S: SLOT7.E11
VI_524_7-CH20BP: SLOT7.C11
VI_524_7-CH20F: SLOT7.E9
VI_524_7-CH20GS: SLOT7.C13
VI_524_7-CH20S: SLOT7.D9
VI_525_7-CH21BP: SLOT7.B9
VI_525_7-CH21F: SLOT7.F9
VI_525_7-CH21GS: SLOT7.B11
VI_525_7-CH21S: SLOT7.C9
VI_526_7-CH22BP: SLOT7.D7
VI_526_7-CH22F: SLOT7.F7
VI_526_7-CH22GS: SLOT7.A11
VI_526_7-CH22S: SLOT7.E7
VI_527_7-CH23BP: SLOT7.D5
VI_527_7-CH23F: SLOT7.F5
VI_527_7-CH23GS: SLOT7.A9
VI_527_7-CH23S: SLOT7.E5
VI_528_7-CH24BP: SLOT7.D3
VI_528_7-CH24F: SLOT7.F3
VI_528_7-CH24GS: SLOT7.A7
VI_528_7-CH24S: SLOT7.E3
VI_529_7-CH25BP: SLOT7.D1
VI_529_7-CH25F: SLOT7.F1
VI_529_7-CH25GS: SLOT7.B7
VI_529_7-CH25S: SLOT7.E1
VI_530_7-CH26BP: SLOT7.C3
VI_530_7-CH26F: SLOT7.G4
VI_530_7-CH26GS: SLOT7.C7
VI_530_7-CH26S: SLOT7.C1
VI_531_7-CH27BP: SLOT7.D2
VI_531_7-CH27F: SLOT7.F2
VI_531_7-CH27GS: SLOT7.C5
VI_531_7-CH27S: SLOT7.C4
VI_532_7-CH28BP: SLOT7.B3
VI_532_7-CH28F: SLOT7.A4
VI_532_7-CH28GS: SLOT7.B5
VI_532_7-CH28S: SLOT7.B1
VI_533_7-CH29BP: SLOT7.A3
VI_533_7-CH29F: SLOT7.B2
VI_533_7-CH29GS: SLOT7.A5
VI_533_7-CH29S: SLOT7.A1
VI_534_7-CH30BP: SLOT7.A60
VI_534_7-CH30F: SLOT7.B62
VI_534_7-CH30GS: SLOT7.B58
VI_534_7-CH30S: SLOT7.A61
VI_535_7-CH31BP: SLOT7.A59
VI_535_7-CH31F: SLOT7.C62
VI_535_7-CH31GS: SLOT7.A57
VI_535_7-CH31S: SLOT7.B61
VI_536_7-CH32BP: SLOT7.E60
VI_536_7-CH32F: SLOT7.F62
VI_536_7-CH32GS: SLOT7.C60
VI_536_7-CH32S: SLOT7.F61
VI_537_7-CH33BP: SLOT7.D61
VI_537_7-CH33F: SLOT7.E62
VI_537_7-CH33GS: SLOT7.C61
VI_537_7-CH33S: SLOT7.E61
VI_538_7-CH34BP: SLOT7.C59
VI_538_7-CH34F: SLOT7.F59
VI_538_7-CH34GS: SLOT7.B59
VI_538_7-CH34S: SLOT7.D59
VI_539_7-CH35BP: SLOT7.F58
VI_539_7-CH35F: SLOT7.G60
VI_539_7-CH35GS: SLOT7.D58
VI_539_7-CH35S: SLOT7.E59
VI_540_7-CH36BP: SLOT7.C57
VI_540_7-CH36F: SLOT7.E57
VI_540_7-CH36GS: SLOT7.B57
VI_540_7-CH36S: SLOT7.D57
VI_541_7-CH37BP: SLOT7.E56
VI_541_7-CH37F: SLOT7.F57
VI_541_7-CH37GS: SLOT7.C56
VI_541_7-CH37S: SLOT7.G56
VI_542_7-CH38BP: SLOT7.D55
VI_542_7-CH38F: SLOT7.F55
VI_542_7-CH38GS: SLOT7.B55
VI_542_7-CH38S: SLOT7.E55
VI_543_7-CH39BP: SLOT7.B54
VI_543_7-CH39F: SLOT7.E52
VI_543_7-CH39GS: SLOT7.A55
VI_543_7-CH39S: SLOT7.C55
VI_544_7-CH40BP: SLOT7.D54
VI_544_7-CH40F: SLOT7.G52
VI_544_7-CH40GS: SLOT7.A56
VI_544_7-CH40S: SLOT7.F54
VI_545_7-CH41BP: SLOT7.B53
VI_545_7-CH41F: SLOT7.F53
VI_545_7-CH41GS: SLOT7.A53
VI_545_7-CH41S: SLOT7.C53
VI_546_7-CH42BP: SLOT7.D53
VI_546_7-CH42F: SLOT7.F51
VI_546_7-CH42GS: SLOT7.A52
VI_546_7-CH42S: SLOT7.E53
VI_547_7-CH43BP: SLOT7.C51
VI_547_7-CH43F: SLOT7.E51
VI_547_7-CH43GS: SLOT7.C52
VI_547_7-CH43S: SLOT7.D51
VI_548_7-CH44BP: SLOT7.D50
VI_548_7-CH44F: SLOT7.F49
VI_548_7-CH44GS: SLOT7.A51
VI_548_7-CH44S: SLOT7.F50
VI_549_7-CH45BP: SLOT7.B50
VI_549_7-CH45F: SLOT7.E49
VI_549_7-CH45GS: SLOT7.B51
VI_549_7-CH45S: SLOT7.D49
VI_550_7-CH46BP: SLOT7.B49
VI_550_7-CH46F: SLOT7.G48
VI_550_7-CH46GS: SLOT7.A49
VI_550_7-CH46S: SLOT7.C49
VI_551_7-CH47BP: SLOT7.D47
VI_551_7-CH47F: SLOT7.F47
VI_551_7-CH47GS: SLOT7.A48
VI_551_7-CH47S: SLOT7.E47
VI_552_7-CH48BP: SLOT7.C45
VI_552_7-CH48F: SLOT7.F45
VI_552_7-CH48GS: SLOT7.C48
VI_552_7-CH48S: SLOT7.D46
VI_553_7-CH49BP: SLOT7.C47
VI_553_7-CH49F: SLOT7.F46
VI_553_7-CH49GS: SLOT7.E48
VI_553_7-CH49S: SLOT7.E45
VI_554_7-CH50BP: SLOT7.B46
VI_554_7-CH50F: SLOT7.G44
VI_554_7-CH50GS: SLOT7.B47
VI_554_7-CH50S: SLOT7.B45
VI_555_7-CH51BP: SLOT7.D45
VI_555_7-CH51F: SLOT7.F41
VI_555_7-CH51GS: SLOT7.A47
VI_555_7-CH51S: SLOT7.E43
VI_556_7-CH52BP: SLOT7.D43
VI_556_7-CH52F: SLOT7.F43
VI_556_7-CH52GS: SLOT7.A45
VI_556_7-CH52S: SLOT7.F42
VI_557_7-CH53BP: SLOT7.D42
VI_557_7-CH53F: SLOT7.G40
VI_557_7-CH53GS: SLOT7.A44
VI_557_7-CH53S: SLOT7.E41
VI_558_7-CH54BP: SLOT7.C41
VI_558_7-CH54F: SLOT7.F39
VI_558_7-CH54GS: SLOT7.C44
VI_558_7-CH54S: SLOT7.D41
VI_559_7-CH55BP: SLOT7.B41
VI_559_7-CH55F: SLOT7.F38
VI_559_7-CH55GS: SLOT7.E44
VI_559_7-CH55S: SLOT7.B39
VI_560_7-CH56BP: SLOT7.C39
VI_560_7-CH56F: SLOT7.E39
VI_560_7-CH56GS: SLOT7.C43
VI_560_7-CH56S: SLOT7.D39
VI_561_7-CH57BP: SLOT7.A41
VI_561_7-CH57F: SLOT7.E40
VI_561_7-CH57GS: SLOT7.B43
VI_561_7-CH57S: SLOT7.A39
VI_562_7-CH58BP: SLOT7.B42
VI_562_7-CH58F: SLOT7.C40
VI_562_7-CH58GS: SLOT7.A43
VI_562_7-CH58S: SLOT7.A40
VI_563_7-CH59BP: SLOT7.C36
VI_563_7-CH59F: SLOT7.G36
VI_563_7-CH59GS: SLOT7.D38
VI_563_7-CH59S: SLOT7.E36
VI_564_7-CH60BP: SLOT7.D34
VI_564_7-CH60F: SLOT7.G32
VI_564_7-CH60GS: SLOT7.B38
VI_564_7-CH60S: SLOT7.E32
VI_565_7-CH61BP: SLOT7.E24
VI_565_7-CH61F: SLOT7.E28
VI_565_7-CH61GS: SLOT7.A36
VI_565_7-CH61S: SLOT7.F26
VI_566_7-CH62BP: SLOT7.F18
VI_566_7-CH62F: SLOT7.G20
VI_566_7-CH62GS: SLOT7.B10
VI_566_7-CH62S: SLOT7.E16
VI_567_7-CH63BP: SLOT7.E12
VI_567_7-CH63F: SLOT7.F14
VI_567_7-CH63GS: SLOT7.A8
VI_567_7-CH63S: SLOT7.D10
VI_568_7-CH64BP: SLOT7.E8
VI_568_7-CH64F: SLOT7.G8
VI_568_7-CH64GS: SLOT7.C8
VI_568_7-CH64S: SLOT7.F6
VI_569_7-CH65BP: SLOT7.B34
VI_569_7-CH65F: SLOT7.F34
VI_569_7-CH65GS: SLOT7.A32
VI_569_7-CH65S: SLOT7.C32
VI_570_7-CH66BP: SLOT7.D30
VI_570_7-CH66F: SLOT7.F30
VI_570_7-CH66GS: SLOT7.B30
VI_570_7-CH66S: SLOT7.C28
VI_571_7-CH67BP: SLOT7.B26
VI_571_7-CH67F: SLOT7.G28
VI_571_7-CH67GS: SLOT7.A28
VI_571_7-CH67S: SLOT7.D26
VI_572_7-CH68BP: SLOT7.C24
VI_572_7-CH68F: SLOT7.G24
VI_572_7-CH68GS: SLOT7.A24
VI_572_7-CH68S: SLOT7.B22
VI_573_7-CH69BP: SLOT7.C20
VI_573_7-CH69F: SLOT7.F22
VI_573_7-CH69GS: SLOT7.A20
VI_573_7-CH69S: SLOT7.D22
VI_574_7-CH70BP: SLOT7.D18
VI_574_7-CH70F: SLOT7.G16
VI_574_7-CH70GS: SLOT7.B18
VI_574_7-CH70S: SLOT7.E20
VI_575_7-CH71BP: SLOT7.C16
VI_575_7-CH71F: SLOT7.G12
VI_575_7-CH71GS: SLOT7.A16
VI_575_7-CH71S: SLOT7.B14
VI_576_7-CH72BP: SLOT7.C12
VI_576_7-CH72F: SLOT7.F10
VI_576_7-CH72GS: SLOT7.A12
VI_576_7-CH72S: SLOT7.D14
VI_577_8-CH1BP: SLOT8.B35
VI_577_8-CH1F: SITE8.F4(LSIN1 / ILIM0_F) SLOT8.F35 UNK8CS4.2 UNK8SH35.2 UNK8TP_LSIN1_F.1
VI_577_8-CH1GS: SLOT8.A35 UNK8SH39.1
VI_577_8-CH1S: SITE8.S4(LSIN1 / ILIM0_S) SLOT8.C35 UNK8TP_LSIN1_S.1
VI_578_8-CH2BP: SLOT8.B33
VI_578_8-CH2F: SITE8.F23(SW_F) SLOT8.F33 UNK8CS23.1 UNK8TP_SW_F.1
VI_578_8-CH2GS: SLOT8.A33 UNK8SH34.2
VI_578_8-CH2S: SITE8.S23(SW_S) SLOT8.C33 UNK8TP_SW_S.1
VI_579_8-CH3BP: SLOT8.B31
VI_579_8-CH3F: SITE8.F22(VOUT_F) SLOT8.F31 UNK8CS22.1 UNK8TP_VOUT_F.1
VI_579_8-CH3GS: SLOT8.A31 UNK8SH33.2
VI_579_8-CH3S: SITE8.S22(VOUT_S) SLOT8.C31 UNK8TP_VOUT_S.1
VI_580_8-CH4BP: SLOT8.B29
VI_580_8-CH4F: SITE8.F21(VDDIO_F) SLOT8.F29 UNK8C1.1 UNK8CS21.1 UNK8R7.1 UNK8R8.1 UNK8TP_VDDIO_F.1
VI_580_8-CH4GS: SLOT8.A29 UNK8SH20.2
VI_580_8-CH4S: SITE8.S21(VDDIO_S) SLOT8.C29 UNK8TP_VDDIO_S.1
VI_581_8-CH5BP: SLOT8.B27
VI_581_8-CH5F: SITE8.F28(VBUS_F) SLOT8.F25 SLOT8.F27 UNK8CS28.1 UNK8K1.4 UNK8TP_VBUS_F.1
VI_581_8-CH5GS: SLOT8.A25 SLOT8.A27 UNK8SH2.2
VI_581_8-CH5S: SITE8.S28(VBUS_S) SLOT8.C25 SLOT8.C27 UNK8TP_VBUS_S.1
VI_582_8-CH6BP: SLOT8.B25
VI_583_8-CH7BP: SLOT8.B23
VI_583_8-CH7F: SITE8.F20(LSIN2 / NCHGEN_F) SLOT8.F23 UNK8C12.1 UNK8CS20.1 UNK8SH37.2 UNK8TP_LSIN2/NCHGEN_F.1
VI_583_8-CH7GS: SLOT8.A23 UNK8SH29.2
VI_583_8-CH7S: SITE8.S20(LSIN2 / NCHGEN_S) SLOT8.C23 UNK8TP_LSIN2/NCHGEN_S.1
VI_584_8-CH8BP: SLOT8.B21
VI_584_8-CH8F: SLOT8.F21
VI_584_8-CH8GS: SLOT8.A21
VI_584_8-CH8S: SLOT8.C21
VI_585_8-CH9BP: SLOT8.D37
VI_585_8-CH9F: SITE6.F4(LSIN1 / ILIM0_F) SLOT8.F37 UNK6CS4.2 UNK6SH35.2 UNK6TP_LSIN1_F.1
VI_585_8-CH9GS: SLOT8.C37 UNK6SH39.1
VI_585_8-CH9S: SITE6.S4(LSIN1 / ILIM0_S) SLOT8.E37 UNK6TP_LSIN1_S.1
VI_586_8-CH10BP: SLOT8.D33
VI_586_8-CH10F: SITE6.F23(SW_F) SLOT8.E35 UNK6CS23.1 UNK6TP_SW_F.1
VI_586_8-CH10GS: SLOT8.B37 UNK6SH34.2
VI_586_8-CH10S: SITE6.S23(SW_S) SLOT8.E33 UNK6TP_SW_S.1
VI_587_8-CH11BP: SLOT8.D29
VI_587_8-CH11F: SITE6.F22(VOUT_F) SLOT8.E31 UNK6CS22.1 UNK6TP_VOUT_F.1
VI_587_8-CH11GS: SLOT8.A37 UNK6SH33.2
VI_587_8-CH11S: SITE6.S22(VOUT_S) SLOT8.E29 UNK6TP_VOUT_S.1
VI_588_8-CH12BP: SLOT8.D25
VI_588_8-CH12F: SITE6.F21(VDDIO_F) SLOT8.E27 UNK6C1.1 UNK6CS21.1 UNK6R7.1 UNK6R8.1 UNK6TP_VDDIO_F.1
VI_588_8-CH12GS: SLOT8.B19 UNK6SH20.2
VI_588_8-CH12S: SITE6.S21(VDDIO_S) SLOT8.E25 UNK6TP_VDDIO_S.1
VI_589_8-CH13BP: SLOT8.D21
VI_589_8-CH13F: SITE6.F28(VBUS_F) SLOT8.E23 SLOT8.F19 UNK6CS28.1 UNK6K1.4 UNK6TP_VBUS_F.1
VI_589_8-CH13GS: SLOT8.A19 SLOT8.C19 UNK6SH2.2
VI_589_8-CH13S: SITE6.S28(VBUS_S) SLOT8.E19 SLOT8.E21 UNK6TP_VBUS_S.1
VI_590_8-CH14BP: SLOT8.D19
VI_591_8-CH15BP: SLOT8.D17
VI_591_8-CH15F: SITE6.F20(LSIN2 / NCHGEN_F) SLOT8.F17 UNK6C12.1 UNK6CS20.1 UNK6SH37.2 UNK6TP_LSIN2/NCHGEN_F.1
VI_591_8-CH15GS: SLOT8.A17 UNK6SH29.2
VI_591_8-CH15S: SITE6.S20(LSIN2 / NCHGEN_S) SLOT8.E17 UNK6TP_LSIN2/NCHGEN_S.1
VI_592_8-CH16BP: SLOT8.C17
VI_592_8-CH16F: SLOT8.E15
VI_592_8-CH16GS: SLOT8.B17
VI_592_8-CH16S: SLOT8.D15
VI_593_8-CH17BP: SLOT8.B15
VI_593_8-CH17F: SITE2.F4(LSIN1 / ILIM0_F) SLOT8.F15 UNK2CS4.2 UNK2SH35.2 UNK2TP_LSIN1_F.1
VI_593_8-CH17GS: SLOT8.A15 UNK2SH39.1
VI_593_8-CH17S: SITE2.S4(LSIN1 / ILIM0_S) SLOT8.C15 UNK2TP_LSIN1_S.1
VI_594_8-CH18BP: SLOT8.D13
VI_594_8-CH18F: SITE2.F23(SW_F) SLOT8.F13 UNK2CS23.1 UNK2TP_SW_F.1
VI_594_8-CH18GS: SLOT8.A13 UNK2SH34.2
VI_594_8-CH18S: SITE2.S23(SW_S) SLOT8.E13 UNK2TP_SW_S.1
VI_595_8-CH19BP: SLOT8.D11
VI_595_8-CH19F: SITE2.F22(VOUT_F) SLOT8.F11 UNK2CS22.1 UNK2TP_VOUT_F.1
VI_595_8-CH19GS: SLOT8.B13 UNK2SH33.2
VI_595_8-CH19S: SITE2.S22(VOUT_S) SLOT8.E11 UNK2TP_VOUT_S.1
VI_596_8-CH20BP: SLOT8.C11
VI_596_8-CH20F: SITE2.F21(VDDIO_F) SLOT8.E9 UNK2C1.1 UNK2CS21.1 UNK2R7.1 UNK2R8.1 UNK2TP_VDDIO_F.1
VI_596_8-CH20GS: SLOT8.C13 UNK2SH20.2
VI_596_8-CH20S: SITE2.S21(VDDIO_S) SLOT8.D9 UNK2TP_VDDIO_S.1
VI_597_8-CH21BP: SLOT8.B9
VI_597_8-CH21F: SITE2.F28(VBUS_F) SLOT8.F7 SLOT8.F9 UNK2CS28.1 UNK2K1.4 UNK2TP_VBUS_F.1
VI_597_8-CH21GS: SLOT8.A11 SLOT8.B11 UNK2SH2.2
VI_597_8-CH21S: SITE2.S28(VBUS_S) SLOT8.C9 SLOT8.E7 UNK2TP_VBUS_S.1
VI_598_8-CH22BP: SLOT8.D7
VI_599_8-CH23BP: SLOT8.D5
VI_599_8-CH23F: SITE2.F20(LSIN2 / NCHGEN_F) SLOT8.F5 UNK2C12.1 UNK2CS20.1 UNK2SH37.2 UNK2TP_LSIN2/NCHGEN_F.1
VI_599_8-CH23GS: SLOT8.A9 UNK2SH29.2
VI_599_8-CH23S: SITE2.S20(LSIN2 / NCHGEN_S) SLOT8.E5 UNK2TP_LSIN2/NCHGEN_S.1
VI_600_8-CH24BP: SLOT8.D3
VI_600_8-CH24F: SLOT8.F3
VI_600_8-CH24GS: SLOT8.A7
VI_600_8-CH24S: SLOT8.E3
VI_601_8-CH25BP: SLOT8.D1
VI_601_8-CH25F: SLOT8.F1
VI_601_8-CH25GS: SLOT8.B7
VI_601_8-CH25S: SLOT8.E1
VI_602_8-CH26BP: SLOT8.C3
VI_602_8-CH26F: SLOT8.G4
VI_602_8-CH26GS: SLOT8.C7
VI_602_8-CH26S: SLOT8.C1
VI_603_8-CH27BP: SLOT8.D2
VI_603_8-CH27F: SLOT8.F2
VI_603_8-CH27GS: SLOT8.C5
VI_603_8-CH27S: SLOT8.C4
VI_604_8-CH28BP: SLOT8.B3
VI_604_8-CH28F: SLOT8.A4
VI_604_8-CH28GS: SLOT8.B5
VI_604_8-CH28S: SLOT8.B1
VI_605_8-CH29BP: SLOT8.A3
VI_605_8-CH29F: SLOT8.B2
VI_605_8-CH29GS: SLOT8.A5
VI_605_8-CH29S: SLOT8.A1
VI_606_8-CH30BP: SLOT8.A60
VI_606_8-CH30F: SLOT8.B62
VI_606_8-CH30GS: SLOT8.B58
VI_606_8-CH30S: SLOT8.A61
VI_607_8-CH31BP: SLOT8.A59
VI_607_8-CH31F: SLOT8.C62
VI_607_8-CH31GS: SLOT8.A57
VI_607_8-CH31S: SLOT8.B61
VI_608_8-CH32BP: SLOT8.E60
VI_608_8-CH32F: SLOT8.F62
VI_608_8-CH32GS: SLOT8.C60
VI_608_8-CH32S: SLOT8.F61
VI_609_8-CH33BP: SLOT8.D61
VI_609_8-CH33F: SITE16.F4(LSIN1 / ILIM0_F) SLOT8.E62 UNK16CS4.2 UNK16SH35.2 UNK16TP_LSIN1_F.1
VI_609_8-CH33GS: SLOT8.C61 UNK16SH39.1
VI_609_8-CH33S: SITE16.S4(LSIN1 / ILIM0_S) SLOT8.E61 UNK16TP_LSIN1_S.1
VI_610_8-CH34BP: SLOT8.C59
VI_610_8-CH34F: SITE16.F23(SW_F) SLOT8.F59 UNK16CS23.1 UNK16TP_SW_F.1
VI_610_8-CH34GS: SLOT8.B59 UNK16SH34.2
VI_610_8-CH34S: SITE16.S23(SW_S) SLOT8.D59 UNK16TP_SW_S.1
VI_611_8-CH35BP: SLOT8.F58
VI_611_8-CH35F: SITE16.F22(VOUT_F) SLOT8.G60 UNK16CS22.1 UNK16TP_VOUT_F.1
VI_611_8-CH35GS: SLOT8.D58 UNK16SH33.2
VI_611_8-CH35S: SITE16.S22(VOUT_S) SLOT8.E59 UNK16TP_VOUT_S.1
VI_612_8-CH36BP: SLOT8.C57
VI_612_8-CH36F: SITE16.F21(VDDIO_F) SLOT8.E57 UNK16C1.1 UNK16CS21.1 UNK16R7.1 UNK16R8.1 UNK16TP_VDDIO_F.1
VI_612_8-CH36GS: SLOT8.B57 UNK16SH20.2
VI_612_8-CH36S: SITE16.S21(VDDIO_S) SLOT8.D57 UNK16TP_VDDIO_S.1
VI_613_8-CH37BP: SLOT8.E56
VI_613_8-CH37F: SITE16.F28(VBUS_F) SLOT8.F55 SLOT8.F57 UNK16CS28.1 UNK16K1.4 UNK16TP_VBUS_F.1
VI_613_8-CH37GS: SLOT8.B55 SLOT8.C56 UNK16SH2.2
VI_613_8-CH37S: SITE16.S28(VBUS_S) SLOT8.E55 SLOT8.G56 UNK16TP_VBUS_S.1
VI_614_8-CH38BP: SLOT8.D55
VI_615_8-CH39BP: SLOT8.B54
VI_615_8-CH39F: SITE16.F20(LSIN2 / NCHGEN_F) SLOT8.E52 UNK16C12.1 UNK16CS20.1 UNK16SH37.2 UNK16TP_LSIN2/NCHGEN_F.1
VI_615_8-CH39GS: SLOT8.A55 UNK16SH29.2
VI_615_8-CH39S: SITE16.S20(LSIN2 / NCHGEN_S) SLOT8.C55 UNK16TP_LSIN2/NCHGEN_S.1
VI_616_8-CH40BP: SLOT8.D54
VI_616_8-CH40F: SLOT8.G52
VI_616_8-CH40GS: SLOT8.A56
VI_616_8-CH40S: SLOT8.F54
VI_617_8-CH41BP: SLOT8.B53
VI_617_8-CH41F: SITE14.F4(LSIN1 / ILIM0_F) SLOT8.F53 UNK14CS4.2 UNK14SH35.2 UNK14TP_LSIN1_F.1
VI_617_8-CH41GS: SLOT8.A53 UNK14SH39.1
VI_617_8-CH41S: SITE14.S4(LSIN1 / ILIM0_S) SLOT8.C53 UNK14TP_LSIN1_S.1
VI_618_8-CH42BP: SLOT8.D53
VI_618_8-CH42F: SITE14.F23(SW_F) SLOT8.F51 UNK14CS23.1 UNK14TP_SW_F.1
VI_618_8-CH42GS: SLOT8.A52 UNK14SH34.2
VI_618_8-CH42S: SITE14.S23(SW_S) SLOT8.E53 UNK14TP_SW_S.1
VI_619_8-CH43BP: SLOT8.C51
VI_619_8-CH43F: SITE14.F22(VOUT_F) SLOT8.E51 UNK14CS22.1 UNK14TP_VOUT_F.1
VI_619_8-CH43GS: SLOT8.C52 UNK14SH33.2
VI_619_8-CH43S: SITE14.S22(VOUT_S) SLOT8.D51 UNK14TP_VOUT_S.1
VI_620_8-CH44BP: SLOT8.D50
VI_620_8-CH44F: SITE14.F21(VDDIO_F) SLOT8.F49 UNK14C1.1 UNK14CS21.1 UNK14R7.1 UNK14R8.1 UNK14TP_VDDIO_F.1
VI_620_8-CH44GS: SLOT8.A51 UNK14SH20.2
VI_620_8-CH44S: SITE14.S21(VDDIO_S) SLOT8.F50 UNK14TP_VDDIO_S.1
VI_621_8-CH45BP: SLOT8.B50
VI_621_8-CH45F: SITE14.F28(VBUS_F) SLOT8.E49 SLOT8.G48 UNK14CS28.1 UNK14K1.4 UNK14TP_VBUS_F.1
VI_621_8-CH45GS: SLOT8.A49 SLOT8.B51 UNK14SH2.2
VI_621_8-CH45S: SITE14.S28(VBUS_S) SLOT8.C49 SLOT8.D49 UNK14TP_VBUS_S.1
VI_622_8-CH46BP: SLOT8.B49
VI_623_8-CH47BP: SLOT8.D47
VI_623_8-CH47F: SITE14.F20(LSIN2 / NCHGEN_F) SLOT8.F47 UNK14C12.1 UNK14CS20.1 UNK14SH37.2 UNK14TP_LSIN2/NCHGEN_F.1
VI_623_8-CH47GS: SLOT8.A48 UNK14SH29.2
VI_623_8-CH47S: SITE14.S20(LSIN2 / NCHGEN_S) SLOT8.E47 UNK14TP_LSIN2/NCHGEN_S.1
VI_624_8-CH48BP: SLOT8.C45
VI_624_8-CH48F: SLOT8.F45
VI_624_8-CH48GS: SLOT8.C48
VI_624_8-CH48S: SLOT8.D46
VI_625_8-CH49BP: SLOT8.C47
VI_625_8-CH49F: SITE12.F4(LSIN1 / ILIM0_F) SLOT8.F46 UNK12CS4.2 UNK12SH35.2 UNK12TP_LSIN1_F.1
VI_625_8-CH49GS: SLOT8.E48 UNK12SH39.1
VI_625_8-CH49S: SITE12.S4(LSIN1 / ILIM0_S) SLOT8.E45 UNK12TP_LSIN1_S.1
VI_626_8-CH50BP: SLOT8.B46
VI_626_8-CH50F: SITE12.F23(SW_F) SLOT8.G44 UNK12CS23.1 UNK12TP_SW_F.1
VI_626_8-CH50GS: SLOT8.B47 UNK12SH34.2
VI_626_8-CH50S: SITE12.S23(SW_S) SLOT8.B45 UNK12TP_SW_S.1
VI_627_8-CH51BP: SLOT8.D45
VI_627_8-CH51F: SITE12.F22(VOUT_F) SLOT8.F41 UNK12CS22.1 UNK12TP_VOUT_F.1
VI_627_8-CH51GS: SLOT8.A47 UNK12SH33.2
VI_627_8-CH51S: SITE12.S22(VOUT_S) SLOT8.E43 UNK12TP_VOUT_S.1
VI_628_8-CH52BP: SLOT8.D43
VI_628_8-CH52F: SITE12.F21(VDDIO_F) SLOT8.F43 UNK12C1.1 UNK12CS21.1 UNK12R7.1 UNK12R8.1 UNK12TP_VDDIO_F.1
VI_628_8-CH52GS: SLOT8.A45 UNK12SH20.2
VI_628_8-CH52S: SITE12.S21(VDDIO_S) SLOT8.F42 UNK12TP_VDDIO_S.1
VI_629_8-CH53BP: SLOT8.D42
VI_629_8-CH53F: SITE12.F28(VBUS_F) SLOT8.F39 SLOT8.G40 UNK12CS28.1 UNK12K1.4 UNK12TP_VBUS_F.1
VI_629_8-CH53GS: SLOT8.A44 SLOT8.C44 UNK12SH2.2
VI_629_8-CH53S: SITE12.S28(VBUS_S) SLOT8.D41 SLOT8.E41 UNK12TP_VBUS_S.1
VI_630_8-CH54BP: SLOT8.C41
VI_631_8-CH55BP: SLOT8.B41
VI_631_8-CH55F: SITE12.F20(LSIN2 / NCHGEN_F) SLOT8.F38 UNK12C12.1 UNK12CS20.1 UNK12SH37.2 UNK12TP_LSIN2/NCHGEN_F.1
VI_631_8-CH55GS: SLOT8.E44 UNK12SH29.2
VI_631_8-CH55S: SITE12.S20(LSIN2 / NCHGEN_S) SLOT8.B39 UNK12TP_LSIN2/NCHGEN_S.1
VI_632_8-CH56BP: SLOT8.C39
VI_632_8-CH56F: SLOT8.E39
VI_632_8-CH56GS: SLOT8.C43
VI_632_8-CH56S: SLOT8.D39
VI_633_8-CH57BP: SLOT8.A41
VI_633_8-CH57F: SITE10.F4(LSIN1 / ILIM0_F) SLOT8.E40 UNK10CS4.2 UNK10SH35.2 UNK10TP_LSIN1_F.1
VI_633_8-CH57GS: SLOT8.B43 UNK10SH39.1
VI_633_8-CH57S: SITE10.S4(LSIN1 / ILIM0_S) SLOT8.A39 UNK10TP_LSIN1_S.1
VI_634_8-CH58BP: SLOT8.B42
VI_634_8-CH58F: SITE10.F23(SW_F) SLOT8.C40 UNK10CS23.1 UNK10TP_SW_F.1
VI_634_8-CH58GS: SLOT8.A43 UNK10SH34.2
VI_634_8-CH58S: SITE10.S23(SW_S) SLOT8.A40 UNK10TP_SW_S.1
VI_635_8-CH59BP: SLOT8.C36
VI_635_8-CH59F: SITE10.F22(VOUT_F) SLOT8.G36 UNK10CS22.1 UNK10TP_VOUT_F.1
VI_635_8-CH59GS: SLOT8.D38 UNK10SH33.2
VI_635_8-CH59S: SITE10.S22(VOUT_S) SLOT8.E36 UNK10TP_VOUT_S.1
VI_636_8-CH60BP: SLOT8.D34
VI_636_8-CH60F: SITE10.F21(VDDIO_F) SLOT8.G32 UNK10C1.1 UNK10CS21.1 UNK10R7.1 UNK10R8.1 UNK10TP_VDDIO_F.1
VI_636_8-CH60GS: SLOT8.B38 UNK10SH20.2
VI_636_8-CH60S: SITE10.S21(VDDIO_S) SLOT8.E32 UNK10TP_VDDIO_S.1
VI_637_8-CH61BP: SLOT8.E24
VI_637_8-CH61F: SITE10.F28(VBUS_F) SLOT8.E28 SLOT8.G20 UNK10CS28.1 UNK10K1.4 UNK10TP_VBUS_F.1
VI_637_8-CH61GS: SLOT8.A36 SLOT8.B10 UNK10SH2.2
VI_637_8-CH61S: SITE10.S28(VBUS_S) SLOT8.E16 SLOT8.F26 UNK10TP_VBUS_S.1
VI_638_8-CH62BP: SLOT8.F18
VI_639_8-CH63BP: SLOT8.E12
VI_639_8-CH63F: SITE10.F20(LSIN2 / NCHGEN_F) SLOT8.F14 UNK10C12.1 UNK10CS20.1 UNK10SH37.2 UNK10TP_LSIN2/NCHGEN_F.1
VI_639_8-CH63GS: SLOT8.A8 UNK10SH29.2
VI_639_8-CH63S: SITE10.S20(LSIN2 / NCHGEN_S) SLOT8.D10 UNK10TP_LSIN2/NCHGEN_S.1
VI_640_8-CH64BP: SLOT8.E8
VI_640_8-CH64F: SLOT8.G8
VI_640_8-CH64GS: SLOT8.C8
VI_640_8-CH64S: SLOT8.F6
VI_641_8-CH65BP: SLOT8.B34
VI_641_8-CH65F: SITE4.F4(LSIN1 / ILIM0_F) SLOT8.F34 UNK4CS4.2 UNK4SH35.2 UNK4TP_LSIN1_F.1
VI_641_8-CH65GS: SLOT8.A32 UNK4SH39.1
VI_641_8-CH65S: SITE4.S4(LSIN1 / ILIM0_S) SLOT8.C32 UNK4TP_LSIN1_S.1
VI_642_8-CH66BP: SLOT8.D30
VI_642_8-CH66F: SITE4.F23(SW_F) SLOT8.F30 UNK4CS23.1 UNK4TP_SW_F.1
VI_642_8-CH66GS: SLOT8.B30 UNK4SH34.2
VI_642_8-CH66S: SITE4.S23(SW_S) SLOT8.C28 UNK4TP_SW_S.1
VI_643_8-CH67BP: SLOT8.B26
VI_643_8-CH67F: SITE4.F22(VOUT_F) SLOT8.G28 UNK4CS22.1 UNK4TP_VOUT_F.1
VI_643_8-CH67GS: SLOT8.A28 UNK4SH33.2
VI_643_8-CH67S: SITE4.S22(VOUT_S) SLOT8.D26 UNK4TP_VOUT_S.1
VI_644_8-CH68BP: SLOT8.C24
VI_644_8-CH68F: SITE4.F21(VDDIO_F) SLOT8.G24 UNK4C1.1 UNK4CS21.1 UNK4R7.1 UNK4R8.1 UNK4TP_VDDIO_F.1
VI_644_8-CH68GS: SLOT8.A24 UNK4SH20.2
VI_644_8-CH68S: SITE4.S21(VDDIO_S) SLOT8.B22 UNK4TP_VDDIO_S.1
VI_645_8-CH69BP: SLOT8.C20
VI_645_8-CH69F: SITE4.F28(VBUS_F) SLOT8.F22 SLOT8.G16 UNK4CS28.1 UNK4K1.4 UNK4TP_VBUS_F.1
VI_645_8-CH69GS: SLOT8.A20 SLOT8.B18 UNK4SH2.2
VI_645_8-CH69S: SITE4.S28(VBUS_S) SLOT8.D22 SLOT8.E20 UNK4TP_VBUS_S.1
VI_646_8-CH70BP: SLOT8.D18
VI_647_8-CH71BP: SLOT8.C16
VI_647_8-CH71F: SITE4.F20(LSIN2 / NCHGEN_F) SLOT8.G12 UNK4C12.1 UNK4CS20.1 UNK4SH37.2 UNK4TP_LSIN2/NCHGEN_F.1
VI_647_8-CH71GS: SLOT8.A16 UNK4SH29.2
VI_647_8-CH71S: SITE4.S20(LSIN2 / NCHGEN_S) SLOT8.B14 UNK4TP_LSIN2/NCHGEN_S.1
VI_648_8-CH72BP: SLOT8.C12
VI_648_8-CH72F: SLOT8.F10
VI_648_8-CH72GS: SLOT8.A12
VI_648_8-CH72S: SLOT8.D14
VI_649_9-CH1BP: SLOT9.B35
VI_649_9-CH1F: SITE9.F4(LSIN1 / ILIM0_F) SLOT9.F35 UNK9CS4.2 UNK9SH35.2 UNK9TP_LSIN1_F.1
VI_649_9-CH1GS: SLOT9.A35 UNK9SH39.1
VI_649_9-CH1S: SITE9.S4(LSIN1 / ILIM0_S) SLOT9.C35 UNK9TP_LSIN1_S.1
VI_650_9-CH2BP: SLOT9.B33
VI_650_9-CH2F: SITE9.F23(SW_F) SLOT9.F33 UNK9CS23.1 UNK9TP_SW_F.1
VI_650_9-CH2GS: SLOT9.A33 UNK9SH34.2
VI_650_9-CH2S: SITE9.S23(SW_S) SLOT9.C33 UNK9TP_SW_S.1
VI_651_9-CH3BP: SLOT9.B31
VI_651_9-CH3F: SITE9.F22(VOUT_F) SLOT9.F31 UNK9CS22.1 UNK9TP_VOUT_F.1
VI_651_9-CH3GS: SLOT9.A31 UNK9SH33.2
VI_651_9-CH3S: SITE9.S22(VOUT_S) SLOT9.C31 UNK9TP_VOUT_S.1
VI_652_9-CH4BP: SLOT9.B29
VI_652_9-CH4F: SITE9.F21(VDDIO_F) SLOT9.F29 UNK9C1.1 UNK9CS21.1 UNK9R7.1 UNK9R8.1 UNK9TP_VDDIO_F.1
VI_652_9-CH4GS: SLOT9.A29 UNK9SH20.2
VI_652_9-CH4S: SITE9.S21(VDDIO_S) SLOT9.C29 UNK9TP_VDDIO_S.1
VI_653_9-CH5BP: SLOT9.B27
VI_653_9-CH5F: SITE9.F28(VBUS_F) SLOT9.F25 SLOT9.F27 UNK9CS28.1 UNK9K1.4 UNK9TP_VBUS_F.1
VI_653_9-CH5GS: SLOT9.A25 SLOT9.A27 UNK9SH2.2
VI_653_9-CH5S: SITE9.S28(VBUS_S) SLOT9.C25 SLOT9.C27 UNK9TP_VBUS_S.1
VI_654_9-CH6BP: SLOT9.B25
VI_655_9-CH7BP: SLOT9.B23
VI_655_9-CH7F: SITE9.F20(LSIN2 / NCHGEN_F) SLOT9.F23 UNK9C12.1 UNK9CS20.1 UNK9SH37.2 UNK9TP_LSIN2/NCHGEN_F.1
VI_655_9-CH7GS: SLOT9.A23 UNK9SH29.2
VI_655_9-CH7S: SITE9.S20(LSIN2 / NCHGEN_S) SLOT9.C23 UNK9TP_LSIN2/NCHGEN_S.1
VI_656_9-CH8BP: SLOT9.B21
VI_656_9-CH8F: SLOT9.F21
VI_656_9-CH8GS: SLOT9.A21
VI_656_9-CH8S: SLOT9.C21
VI_657_9-CH9BP: SLOT9.D37
VI_657_9-CH9F: SITE11.F4(LSIN1 / ILIM0_F) SLOT9.F37 UNK11CS4.2 UNK11SH35.2 UNK11TP_LSIN1_F.1
VI_657_9-CH9GS: SLOT9.C37 UNK11SH39.1
VI_657_9-CH9S: SITE11.S4(LSIN1 / ILIM0_S) SLOT9.E37 UNK11TP_LSIN1_S.1
VI_658_9-CH10BP: SLOT9.D33
VI_658_9-CH10F: SITE11.F23(SW_F) SLOT9.E35 UNK11CS23.1 UNK11TP_SW_F.1
VI_658_9-CH10GS: SLOT9.B37 UNK11SH34.2
VI_658_9-CH10S: SITE11.S23(SW_S) SLOT9.E33 UNK11TP_SW_S.1
VI_659_9-CH11BP: SLOT9.D29
VI_659_9-CH11F: SITE11.F22(VOUT_F) SLOT9.E31 UNK11CS22.1 UNK11TP_VOUT_F.1
VI_659_9-CH11GS: SLOT9.A37 UNK11SH33.2
VI_659_9-CH11S: SITE11.S22(VOUT_S) SLOT9.E29 UNK11TP_VOUT_S.1
VI_660_9-CH12BP: SLOT9.D25
VI_660_9-CH12F: SITE11.F21(VDDIO_F) SLOT9.E27 UNK11C1.1 UNK11CS21.1 UNK11R7.1 UNK11R8.1 UNK11TP_VDDIO_F.1
VI_660_9-CH12GS: SLOT9.B19 UNK11SH20.2
VI_660_9-CH12S: SITE11.S21(VDDIO_S) SLOT9.E25 UNK11TP_VDDIO_S.1
VI_661_9-CH13BP: SLOT9.D21
VI_661_9-CH13F: SITE11.F28(VBUS_F) SLOT9.E23 SLOT9.F19 UNK11CS28.1 UNK11K1.4 UNK11TP_VBUS_F.1
VI_661_9-CH13GS: SLOT9.A19 SLOT9.C19 UNK11SH2.2
VI_661_9-CH13S: SITE11.S28(VBUS_S) SLOT9.E19 SLOT9.E21 UNK11TP_VBUS_S.1
VI_662_9-CH14BP: SLOT9.D19
VI_663_9-CH15BP: SLOT9.D17
VI_663_9-CH15F: SITE11.F20(LSIN2 / NCHGEN_F) SLOT9.F17 UNK11C12.1 UNK11CS20.1 UNK11SH37.2 UNK11TP_LSIN2/NCHGEN_F.1
VI_663_9-CH15GS: SLOT9.A17 UNK11SH29.2
VI_663_9-CH15S: SITE11.S20(LSIN2 / NCHGEN_S) SLOT9.E17 UNK11TP_LSIN2/NCHGEN_S.1
VI_664_9-CH16BP: SLOT9.C17
VI_664_9-CH16F: SLOT9.E15
VI_664_9-CH16GS: SLOT9.B17
VI_664_9-CH16S: SLOT9.D15
VI_665_9-CH17BP: SLOT9.B15
VI_665_9-CH17F: SITE15.F4(LSIN1 / ILIM0_F) SLOT9.F15 UNK15CS4.2 UNK15SH35.2 UNK15TP_LSIN1_F.1
VI_665_9-CH17GS: SLOT9.A15 UNK15SH39.1
VI_665_9-CH17S: SITE15.S4(LSIN1 / ILIM0_S) SLOT9.C15 UNK15TP_LSIN1_S.1
VI_666_9-CH18BP: SLOT9.D13
VI_666_9-CH18F: SITE15.F23(SW_F) SLOT9.F13 UNK15CS23.1 UNK15TP_SW_F.1
VI_666_9-CH18GS: SLOT9.A13 UNK15SH34.2
VI_666_9-CH18S: SITE15.S23(SW_S) SLOT9.E13 UNK15TP_SW_S.1
VI_667_9-CH19BP: SLOT9.D11
VI_667_9-CH19F: SITE15.F22(VOUT_F) SLOT9.F11 UNK15CS22.1 UNK15TP_VOUT_F.1
VI_667_9-CH19GS: SLOT9.B13 UNK15SH33.2
VI_667_9-CH19S: SITE15.S22(VOUT_S) SLOT9.E11 UNK15TP_VOUT_S.1
VI_668_9-CH20BP: SLOT9.C11
VI_668_9-CH20F: SITE15.F21(VDDIO_F) SLOT9.E9 UNK15C1.1 UNK15CS21.1 UNK15R7.1 UNK15R8.1 UNK15TP_VDDIO_F.1
VI_668_9-CH20GS: SLOT9.C13 UNK15SH20.2
VI_668_9-CH20S: SITE15.S21(VDDIO_S) SLOT9.D9 UNK15TP_VDDIO_S.1
VI_669_9-CH21BP: SLOT9.B9
VI_669_9-CH21F: SITE15.F28(VBUS_F) SLOT9.F7 SLOT9.F9 UNK15CS28.1 UNK15K1.4 UNK15TP_VBUS_F.1
VI_669_9-CH21GS: SLOT9.A11 SLOT9.B11 UNK15SH2.2
VI_669_9-CH21S: SITE15.S28(VBUS_S) SLOT9.C9 SLOT9.E7 UNK15TP_VBUS_S.1
VI_670_9-CH22BP: SLOT9.D7
VI_671_9-CH23BP: SLOT9.D5
VI_671_9-CH23F: SITE15.F20(LSIN2 / NCHGEN_F) SLOT9.F5 UNK15C12.1 UNK15CS20.1 UNK15SH37.2 UNK15TP_LSIN2/NCHGEN_F.1
VI_671_9-CH23GS: SLOT9.A9 UNK15SH29.2
VI_671_9-CH23S: SITE15.S20(LSIN2 / NCHGEN_S) SLOT9.E5 UNK15TP_LSIN2/NCHGEN_S.1
VI_672_9-CH24BP: SLOT9.D3
VI_672_9-CH24F: SLOT9.F3
VI_672_9-CH24GS: SLOT9.A7
VI_672_9-CH24S: SLOT9.E3
VI_673_9-CH25BP: SLOT9.D1
VI_673_9-CH25F: SLOT9.F1
VI_673_9-CH25GS: SLOT9.B7
VI_673_9-CH25S: SLOT9.E1
VI_674_9-CH26BP: SLOT9.C3
VI_674_9-CH26F: SLOT9.G4
VI_674_9-CH26GS: SLOT9.C7
VI_674_9-CH26S: SLOT9.C1
VI_675_9-CH27BP: SLOT9.D2
VI_675_9-CH27F: SLOT9.F2
VI_675_9-CH27GS: SLOT9.C5
VI_675_9-CH27S: SLOT9.C4
VI_676_9-CH28BP: SLOT9.B3
VI_676_9-CH28F: SLOT9.A4
VI_676_9-CH28GS: SLOT9.B5
VI_676_9-CH28S: SLOT9.B1
VI_677_9-CH29BP: SLOT9.A3
VI_677_9-CH29F: SLOT9.B2
VI_677_9-CH29GS: SLOT9.A5
VI_677_9-CH29S: SLOT9.A1
VI_678_9-CH30BP: SLOT9.A60
VI_678_9-CH30F: SLOT9.B62
VI_678_9-CH30GS: SLOT9.B58
VI_678_9-CH30S: SLOT9.A61
VI_679_9-CH31BP: SLOT9.A59
VI_679_9-CH31F: SLOT9.C62
VI_679_9-CH31GS: SLOT9.A57
VI_679_9-CH31S: SLOT9.B61
VI_680_9-CH32BP: SLOT9.E60
VI_680_9-CH32F: SLOT9.F62
VI_680_9-CH32GS: SLOT9.C60
VI_680_9-CH32S: SLOT9.F61
VI_681_9-CH33BP: SLOT9.D61
VI_681_9-CH33F: SITE1.F4(LSIN1 / ILIM0_F) SLOT9.E62 UNK1CS4.2 UNK1SH35.2 UNK1TP_LSIN1_F.1
VI_681_9-CH33GS: SLOT9.C61 UNK1SH39.1
VI_681_9-CH33S: SITE1.S4(LSIN1 / ILIM0_S) SLOT9.E61 UNK1TP_LSIN1_S.1
VI_682_9-CH34BP: SLOT9.C59
VI_682_9-CH34F: SITE1.F23(SW_F) SLOT9.F59 UNK1CS23.1 UNK1TP_SW_F.1
VI_682_9-CH34GS: SLOT9.B59 UNK1SH34.2
VI_682_9-CH34S: SITE1.S23(SW_S) SLOT9.D59 UNK1TP_SW_S.1
VI_683_9-CH35BP: SLOT9.F58
VI_683_9-CH35F: SITE1.F22(VOUT_F) SLOT9.G60 UNK1CS22.1 UNK1TP_VOUT_F.1
VI_683_9-CH35GS: SLOT9.D58 UNK1SH33.2
VI_683_9-CH35S: SITE1.S22(VOUT_S) SLOT9.E59 UNK1TP_VOUT_S.1
VI_684_9-CH36BP: SLOT9.C57
VI_684_9-CH36F: SITE1.F21(VDDIO_F) SLOT9.E57 UNK1C1.1 UNK1CS21.1 UNK1R7.1 UNK1R8.1 UNK1TP_VDDIO_F.1
VI_684_9-CH36GS: SLOT9.B57 UNK1SH20.2
VI_684_9-CH36S: SITE1.S21(VDDIO_S) SLOT9.D57 UNK1TP_VDDIO_S.1
VI_685_9-CH37BP: SLOT9.E56
VI_685_9-CH37F: SITE1.F28(VBUS_F) SLOT9.F55 SLOT9.F57 UNK1CS28.1 UNK1K1.4 UNK1TP_VBUS_F.1
VI_685_9-CH37GS: SLOT9.B55 SLOT9.C56 UNK1SH2.2
VI_685_9-CH37S: SITE1.S28(VBUS_S) SLOT9.E55 SLOT9.G56 UNK1TP_VBUS_S.1
VI_686_9-CH38BP: SLOT9.D55
VI_687_9-CH39BP: SLOT9.B54
VI_687_9-CH39F: SITE1.F20(LSIN2 / NCHGEN_F) SLOT9.E52 UNK1C12.1 UNK1CS20.1 UNK1SH37.2 UNK1TP_LSIN2/NCHGEN_F.1
VI_687_9-CH39GS: SLOT9.A55 UNK1SH29.2
VI_687_9-CH39S: SITE1.S20(LSIN2 / NCHGEN_S) SLOT9.C55 UNK1TP_LSIN2/NCHGEN_S.1
VI_688_9-CH40BP: SLOT9.D54
VI_688_9-CH40F: SLOT9.G52
VI_688_9-CH40GS: SLOT9.A56
VI_688_9-CH40S: SLOT9.F54
VI_689_9-CH41BP: SLOT9.B53
VI_689_9-CH41F: SITE3.F4(LSIN1 / ILIM0_F) SLOT9.F53 UNK3CS4.2 UNK3SH35.2 UNK3TP_LSIN1_F.1
VI_689_9-CH41GS: SLOT9.A53 UNK3SH39.1
VI_689_9-CH41S: SITE3.S4(LSIN1 / ILIM0_S) SLOT9.C53 UNK3TP_LSIN1_S.1
VI_690_9-CH42BP: SLOT9.D53
VI_690_9-CH42F: SITE3.F23(SW_F) SLOT9.F51 UNK3CS23.1 UNK3TP_SW_F.1
VI_690_9-CH42GS: SLOT9.A52 UNK3SH34.2
VI_690_9-CH42S: SITE3.S23(SW_S) SLOT9.E53 UNK3TP_SW_S.1
VI_691_9-CH43BP: SLOT9.C51
VI_691_9-CH43F: SITE3.F22(VOUT_F) SLOT9.E51 UNK3CS22.1 UNK3TP_VOUT_F.1
VI_691_9-CH43GS: SLOT9.C52 UNK3SH33.2
VI_691_9-CH43S: SITE3.S22(VOUT_S) SLOT9.D51 UNK3TP_VOUT_S.1
VI_692_9-CH44BP: SLOT9.D50
VI_692_9-CH44F: SITE3.F21(VDDIO_F) SLOT9.F49 UNK3C1.1 UNK3CS21.1 UNK3R7.1 UNK3R8.1 UNK3TP_VDDIO_F.1
VI_692_9-CH44GS: SLOT9.A51 UNK3SH20.2
VI_692_9-CH44S: SITE3.S21(VDDIO_S) SLOT9.F50 UNK3TP_VDDIO_S.1
VI_693_9-CH45BP: SLOT9.B50
VI_693_9-CH45F: SITE3.F28(VBUS_F) SLOT9.E49 SLOT9.G48 UNK3CS28.1 UNK3K1.4 UNK3TP_VBUS_F.1
VI_693_9-CH45GS: SLOT9.A49 SLOT9.B51 UNK3SH2.2
VI_693_9-CH45S: SITE3.S28(VBUS_S) SLOT9.C49 SLOT9.D49 UNK3TP_VBUS_S.1
VI_694_9-CH46BP: SLOT9.B49
VI_695_9-CH47BP: SLOT9.D47
VI_695_9-CH47F: SITE3.F20(LSIN2 / NCHGEN_F) SLOT9.F47 UNK3C12.1 UNK3CS20.1 UNK3SH37.2 UNK3TP_LSIN2/NCHGEN_F.1
VI_695_9-CH47GS: SLOT9.A48 UNK3SH29.2
VI_695_9-CH47S: SITE3.S20(LSIN2 / NCHGEN_S) SLOT9.E47 UNK3TP_LSIN2/NCHGEN_S.1
VI_696_9-CH48BP: SLOT9.C45
VI_696_9-CH48F: SLOT9.F45
VI_696_9-CH48GS: SLOT9.C48
VI_696_9-CH48S: SLOT9.D46
VI_697_9-CH49BP: SLOT9.C47
VI_697_9-CH49F: SITE5.F4(LSIN1 / ILIM0_F) SLOT9.F46 UNK5CS4.2 UNK5SH35.2 UNK5TP_LSIN1_F.1
VI_697_9-CH49GS: SLOT9.E48 UNK5SH39.1
VI_697_9-CH49S: SITE5.S4(LSIN1 / ILIM0_S) SLOT9.E45 UNK5TP_LSIN1_S.1
VI_698_9-CH50BP: SLOT9.B46
VI_698_9-CH50F: SITE5.F23(SW_F) SLOT9.G44 UNK5CS23.1 UNK5TP_SW_F.1
VI_698_9-CH50GS: SLOT9.B47 UNK5SH34.2
VI_698_9-CH50S: SITE5.S23(SW_S) SLOT9.B45 UNK5TP_SW_S.1
VI_699_9-CH51BP: SLOT9.D45
VI_699_9-CH51F: SITE5.F22(VOUT_F) SLOT9.F41 UNK5CS22.1 UNK5TP_VOUT_F.1
VI_699_9-CH51GS: SLOT9.A47 UNK5SH33.2
VI_699_9-CH51S: SITE5.S22(VOUT_S) SLOT9.E43 UNK5TP_VOUT_S.1
VI_700_9-CH52BP: SLOT9.D43
VI_700_9-CH52F: SITE5.F21(VDDIO_F) SLOT9.F43 UNK5C1.1 UNK5CS21.1 UNK5R7.1 UNK5R8.1 UNK5TP_VDDIO_F.1
VI_700_9-CH52GS: SLOT9.A45 UNK5SH20.2
VI_700_9-CH52S: SITE5.S21(VDDIO_S) SLOT9.F42 UNK5TP_VDDIO_S.1
VI_701_9-CH53BP: SLOT9.D42
VI_701_9-CH53F: SITE5.F28(VBUS_F) SLOT9.F39 SLOT9.G40 UNK5CS28.1 UNK5K1.4 UNK5TP_VBUS_F.1
VI_701_9-CH53GS: SLOT9.A44 SLOT9.C44 UNK5SH2.2
VI_701_9-CH53S: SITE5.S28(VBUS_S) SLOT9.D41 SLOT9.E41 UNK5TP_VBUS_S.1
VI_702_9-CH54BP: SLOT9.C41
VI_703_9-CH55BP: SLOT9.B41
VI_703_9-CH55F: SITE5.F20(LSIN2 / NCHGEN_F) SLOT9.F38 UNK5C12.1 UNK5CS20.1 UNK5SH37.2 UNK5TP_LSIN2/NCHGEN_F.1
VI_703_9-CH55GS: SLOT9.E44 UNK5SH29.2
VI_703_9-CH55S: SITE5.S20(LSIN2 / NCHGEN_S) SLOT9.B39 UNK5TP_LSIN2/NCHGEN_S.1
VI_704_9-CH56BP: SLOT9.C39
VI_704_9-CH56F: SLOT9.E39
VI_704_9-CH56GS: SLOT9.C43
VI_704_9-CH56S: SLOT9.D39
VI_705_9-CH57BP: SLOT9.A41
VI_705_9-CH57F: SITE7.F4(LSIN1 / ILIM0_F) SLOT9.E40 UNK7CS4.2 UNK7SH35.2 UNK7TP_LSIN1_F.1
VI_705_9-CH57GS: SLOT9.B43 UNK7SH39.1
VI_705_9-CH57S: SITE7.S4(LSIN1 / ILIM0_S) SLOT9.A39 UNK7TP_LSIN1_S.1
VI_706_9-CH58BP: SLOT9.B42
VI_706_9-CH58F: SITE7.F23(SW_F) SLOT9.C40 UNK7CS23.1 UNK7TP_SW_F.1
VI_706_9-CH58GS: SLOT9.A43 UNK7SH34.2
VI_706_9-CH58S: SITE7.S23(SW_S) SLOT9.A40 UNK7TP_SW_S.1
VI_707_9-CH59BP: SLOT9.C36
VI_707_9-CH59F: SITE7.F22(VOUT_F) SLOT9.G36 UNK7CS22.1 UNK7TP_VOUT_F.1
VI_707_9-CH59GS: SLOT9.D38 UNK7SH33.2
VI_707_9-CH59S: SITE7.S22(VOUT_S) SLOT9.E36 UNK7TP_VOUT_S.1
VI_708_9-CH60BP: SLOT9.D34
VI_708_9-CH60F: SITE7.F21(VDDIO_F) SLOT9.G32 UNK7C1.1 UNK7CS21.1 UNK7R7.1 UNK7R8.1 UNK7TP_VDDIO_F.1
VI_708_9-CH60GS: SLOT9.B38 UNK7SH20.2
VI_708_9-CH60S: SITE7.S21(VDDIO_S) SLOT9.E32 UNK7TP_VDDIO_S.1
VI_709_9-CH61BP: SLOT9.E24
VI_709_9-CH61F: SITE7.F28(VBUS_F) SLOT9.E28 SLOT9.G20 UNK7CS28.1 UNK7K1.4 UNK7TP_VBUS_F.1
VI_709_9-CH61GS: SLOT9.A36 SLOT9.B10 UNK7SH2.2
VI_709_9-CH61S: SITE7.S28(VBUS_S) SLOT9.E16 SLOT9.F26 UNK7TP_VBUS_S.1
VI_710_9-CH62BP: SLOT9.F18
VI_711_9-CH63BP: SLOT9.E12
VI_711_9-CH63F: SITE7.F20(LSIN2 / NCHGEN_F) SLOT9.F14 UNK7C12.1 UNK7CS20.1 UNK7SH37.2 UNK7TP_LSIN2/NCHGEN_F.1
VI_711_9-CH63GS: SLOT9.A8 UNK7SH29.2
VI_711_9-CH63S: SITE7.S20(LSIN2 / NCHGEN_S) SLOT9.D10 UNK7TP_LSIN2/NCHGEN_S.1
VI_712_9-CH64BP: SLOT9.E8
VI_712_9-CH64F: SLOT9.G8
VI_712_9-CH64GS: SLOT9.C8
VI_712_9-CH64S: SLOT9.F6
VI_713_9-CH65BP: SLOT9.B34
VI_713_9-CH65F: SITE13.F4(LSIN1 / ILIM0_F) SLOT9.F34 UNK13CS4.2 UNK13SH35.2 UNK13TP_LSIN1_F.1
VI_713_9-CH65GS: SLOT9.A32 UNK13SH39.1
VI_713_9-CH65S: SITE13.S4(LSIN1 / ILIM0_S) SLOT9.C32 UNK13TP_LSIN1_S.1
VI_714_9-CH66BP: SLOT9.D30
VI_714_9-CH66F: SITE13.F23(SW_F) SLOT9.F30 UNK13CS23.1 UNK13TP_SW_F.1
VI_714_9-CH66GS: SLOT9.B30 UNK13SH34.2
VI_714_9-CH66S: SITE13.S23(SW_S) SLOT9.C28 UNK13TP_SW_S.1
VI_715_9-CH67BP: SLOT9.B26
VI_715_9-CH67F: SITE13.F22(VOUT_F) SLOT9.G28 UNK13CS22.1 UNK13TP_VOUT_F.1
VI_715_9-CH67GS: SLOT9.A28 UNK13SH33.2
VI_715_9-CH67S: SITE13.S22(VOUT_S) SLOT9.D26 UNK13TP_VOUT_S.1
VI_716_9-CH68BP: SLOT9.C24
VI_716_9-CH68F: SITE13.F21(VDDIO_F) SLOT9.G24 UNK13C1.1 UNK13CS21.1 UNK13R7.1 UNK13R8.1 UNK13TP_VDDIO_F.1
VI_716_9-CH68GS: SLOT9.A24 UNK13SH20.2
VI_716_9-CH68S: SITE13.S21(VDDIO_S) SLOT9.B22 UNK13TP_VDDIO_S.1
VI_717_9-CH69BP: SLOT9.C20
VI_717_9-CH69F: SITE13.F28(VBUS_F) SLOT9.F22 SLOT9.G16 UNK13CS28.1 UNK13K1.4 UNK13TP_VBUS_F.1
VI_717_9-CH69GS: SLOT9.A20 SLOT9.B18 UNK13SH2.2
VI_717_9-CH69S: SITE13.S28(VBUS_S) SLOT9.D22 SLOT9.E20 UNK13TP_VBUS_S.1
VI_718_9-CH70BP: SLOT9.D18
VI_719_9-CH71BP: SLOT9.C16
VI_719_9-CH71F: SITE13.F20(LSIN2 / NCHGEN_F) SLOT9.G12 UNK13C12.1 UNK13CS20.1 UNK13SH37.2 UNK13TP_LSIN2/NCHGEN_F.1
VI_719_9-CH71GS: SLOT9.A16 UNK13SH29.2
VI_719_9-CH71S: SITE13.S20(LSIN2 / NCHGEN_S) SLOT9.B14 UNK13TP_LSIN2/NCHGEN_S.1
VI_720_9-CH72BP: SLOT9.C12
VI_720_9-CH72F: SLOT9.F10
VI_720_9-CH72GS: SLOT9.A12
VI_720_9-CH72S: SLOT9.D14
VOUT_ADJ1-2: C100.1 R376.1 REG1_P_10V.1(TP) U46.2(OUT) U46.4(TAB) U47.3(IN)
N05392: UNK2K7.4 UNK2R41.1
